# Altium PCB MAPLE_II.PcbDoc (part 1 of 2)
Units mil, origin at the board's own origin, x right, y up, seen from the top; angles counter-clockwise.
Board outline 3200 x 2150 mil, 6 copper layers (Top Side, Ground Plane, MidLayer1, MidLayer2, Power Plane, Bottom Side), stack 49.2 mil thick; 130 components, 162 nets, 713 pads, 399 vias.
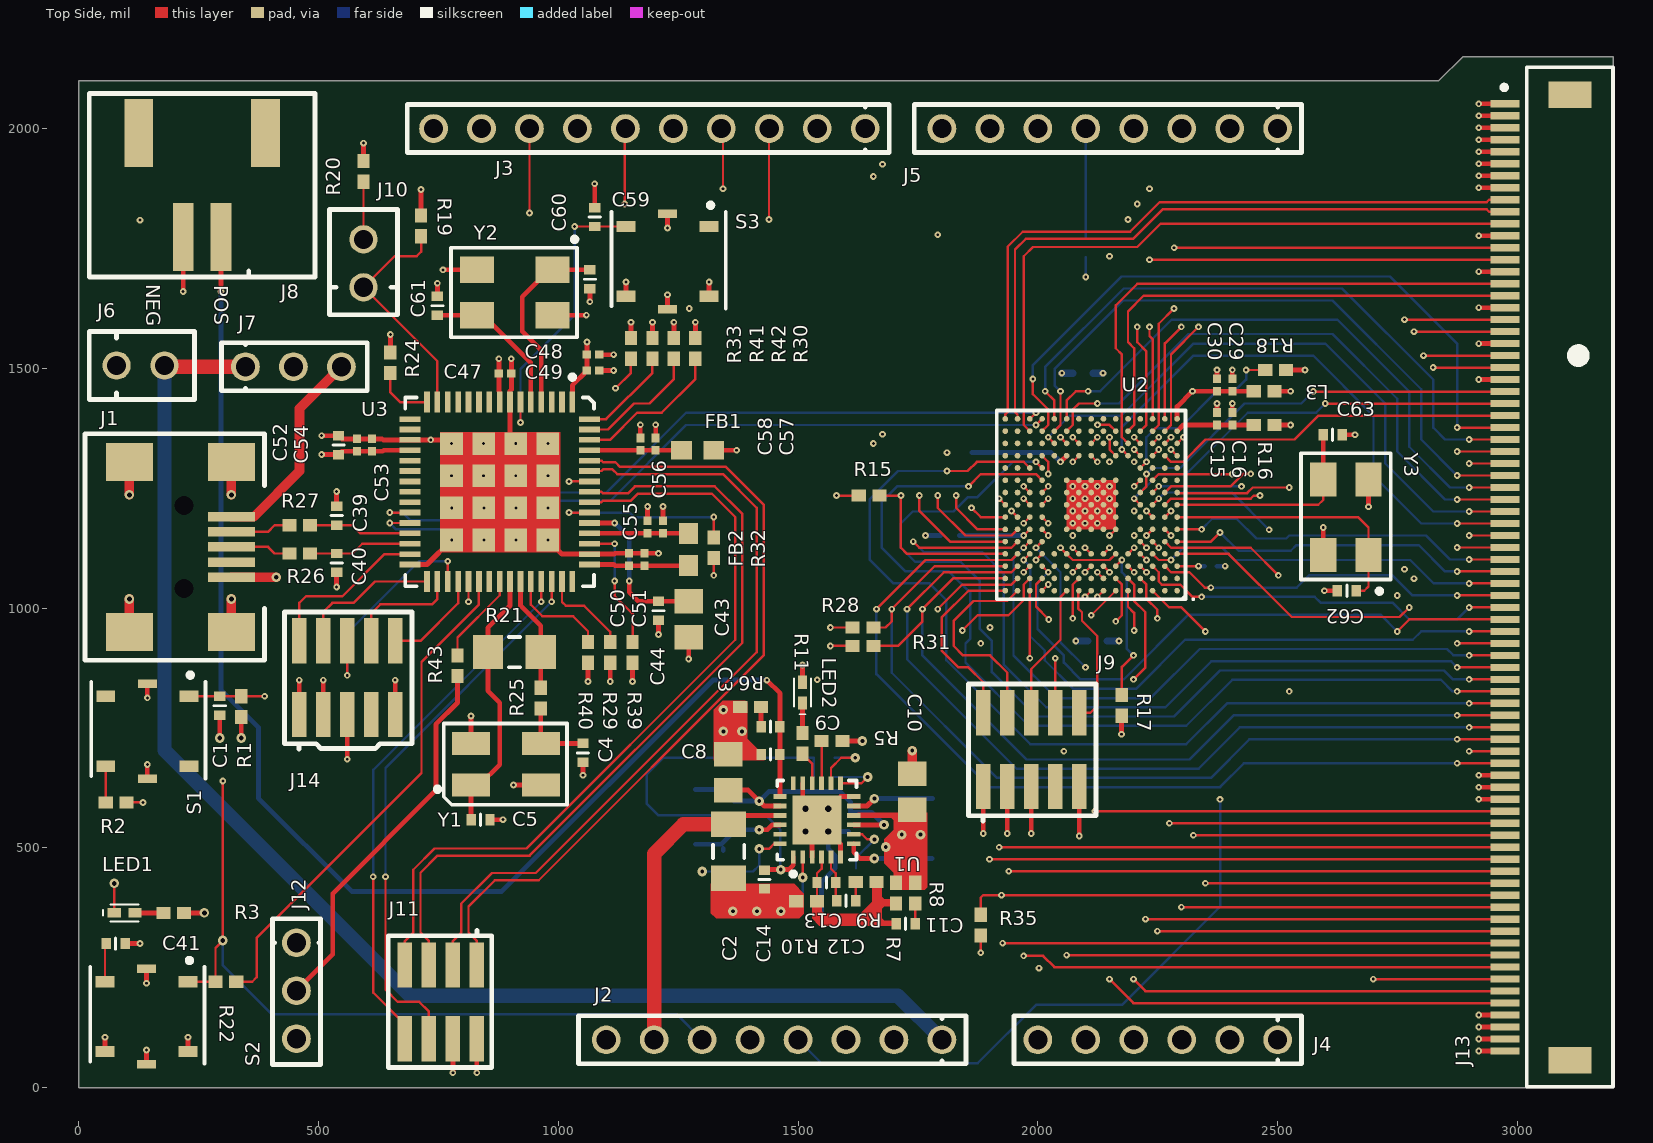
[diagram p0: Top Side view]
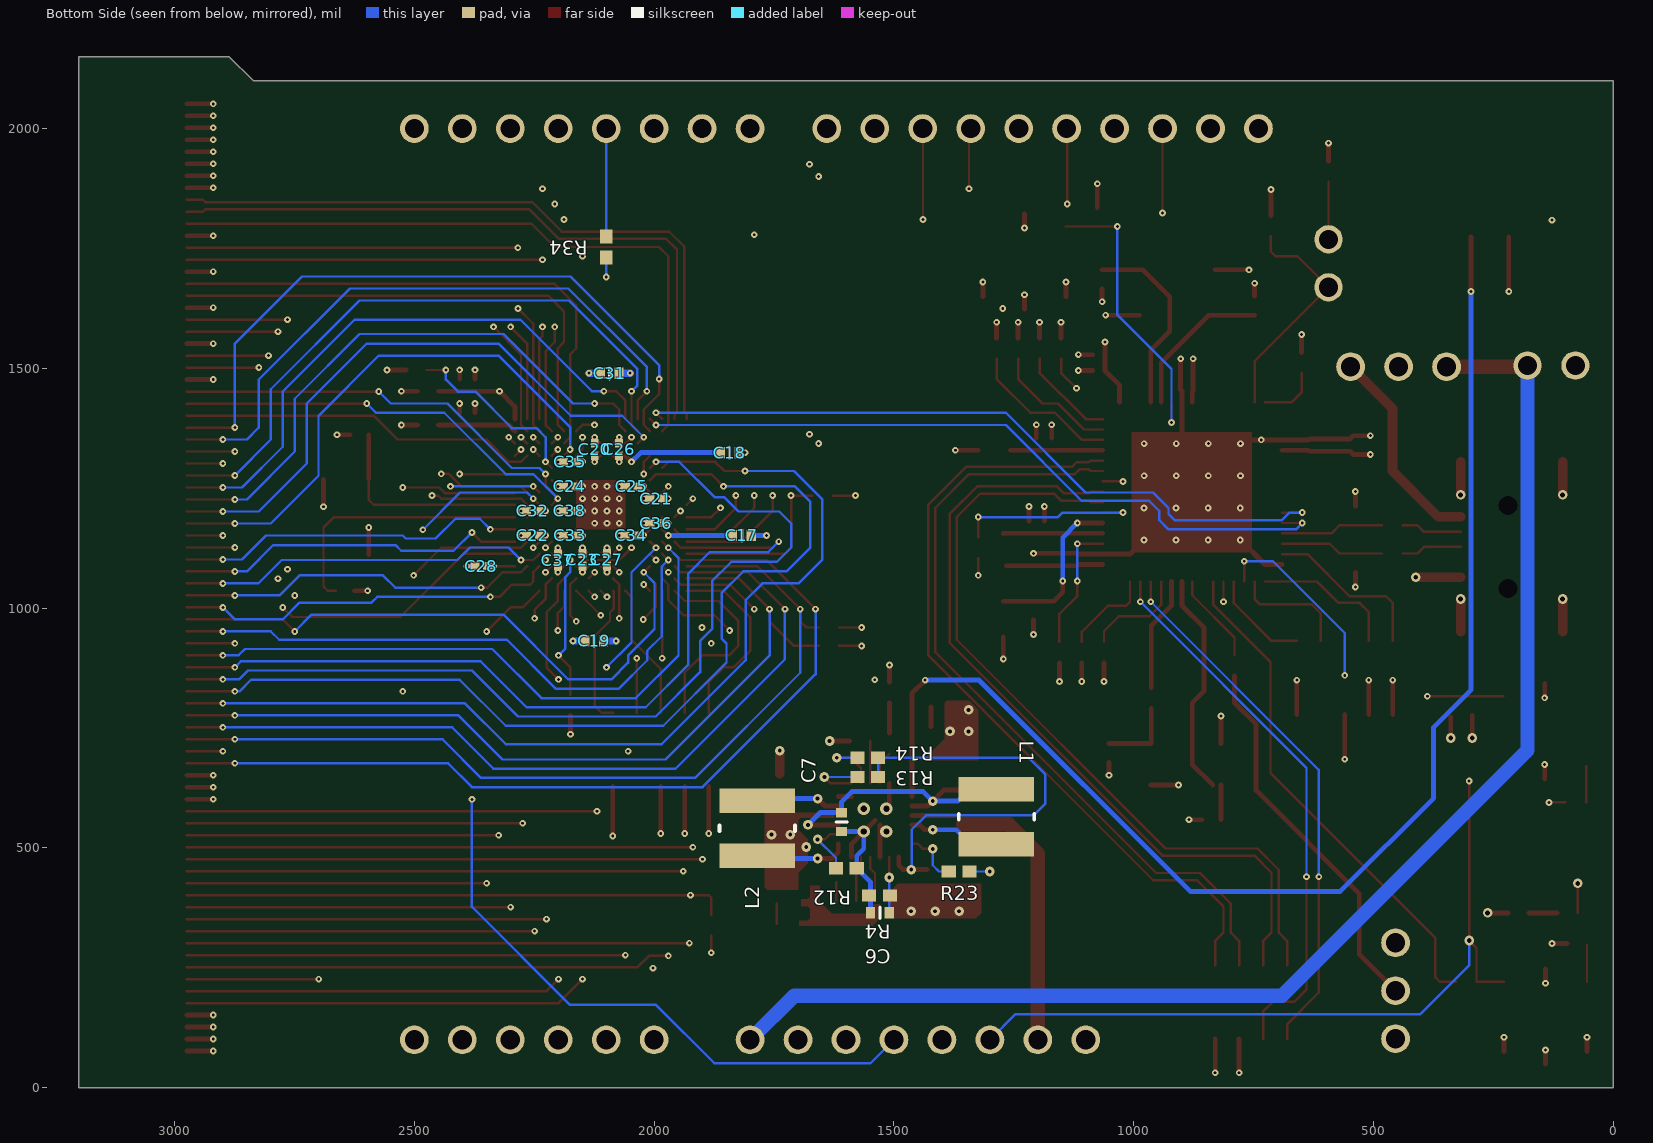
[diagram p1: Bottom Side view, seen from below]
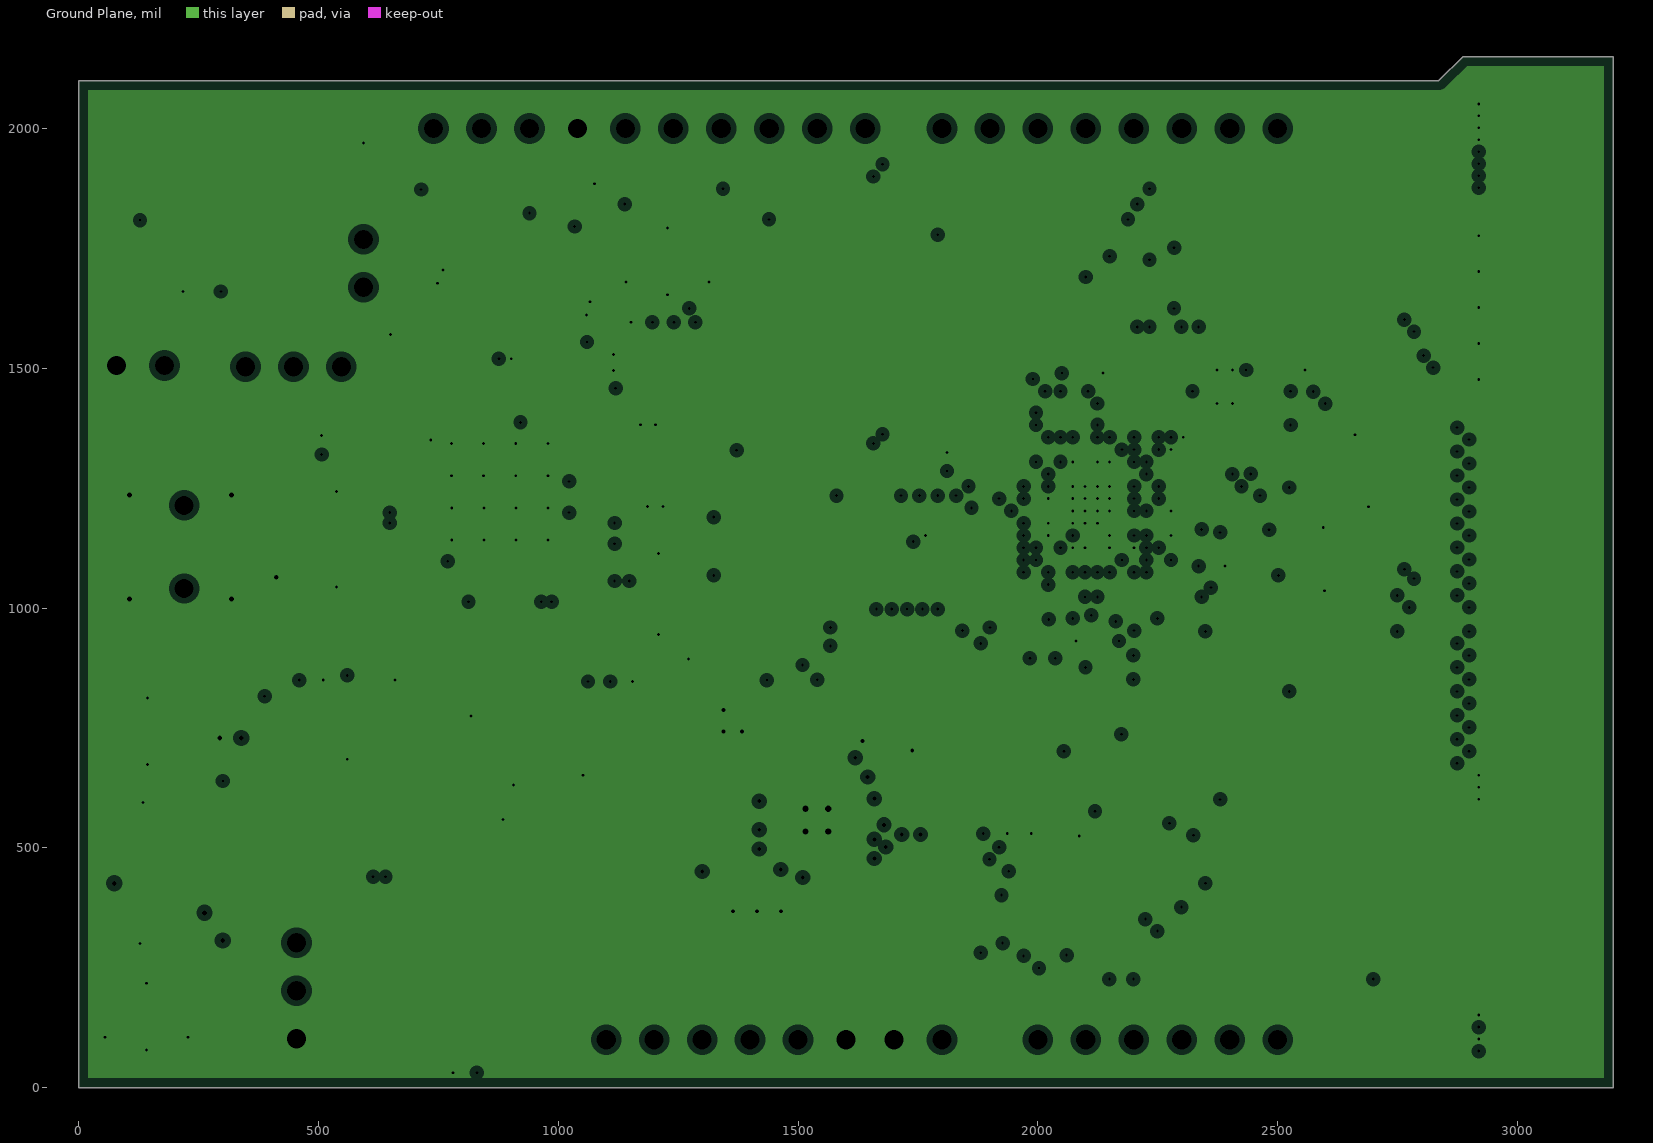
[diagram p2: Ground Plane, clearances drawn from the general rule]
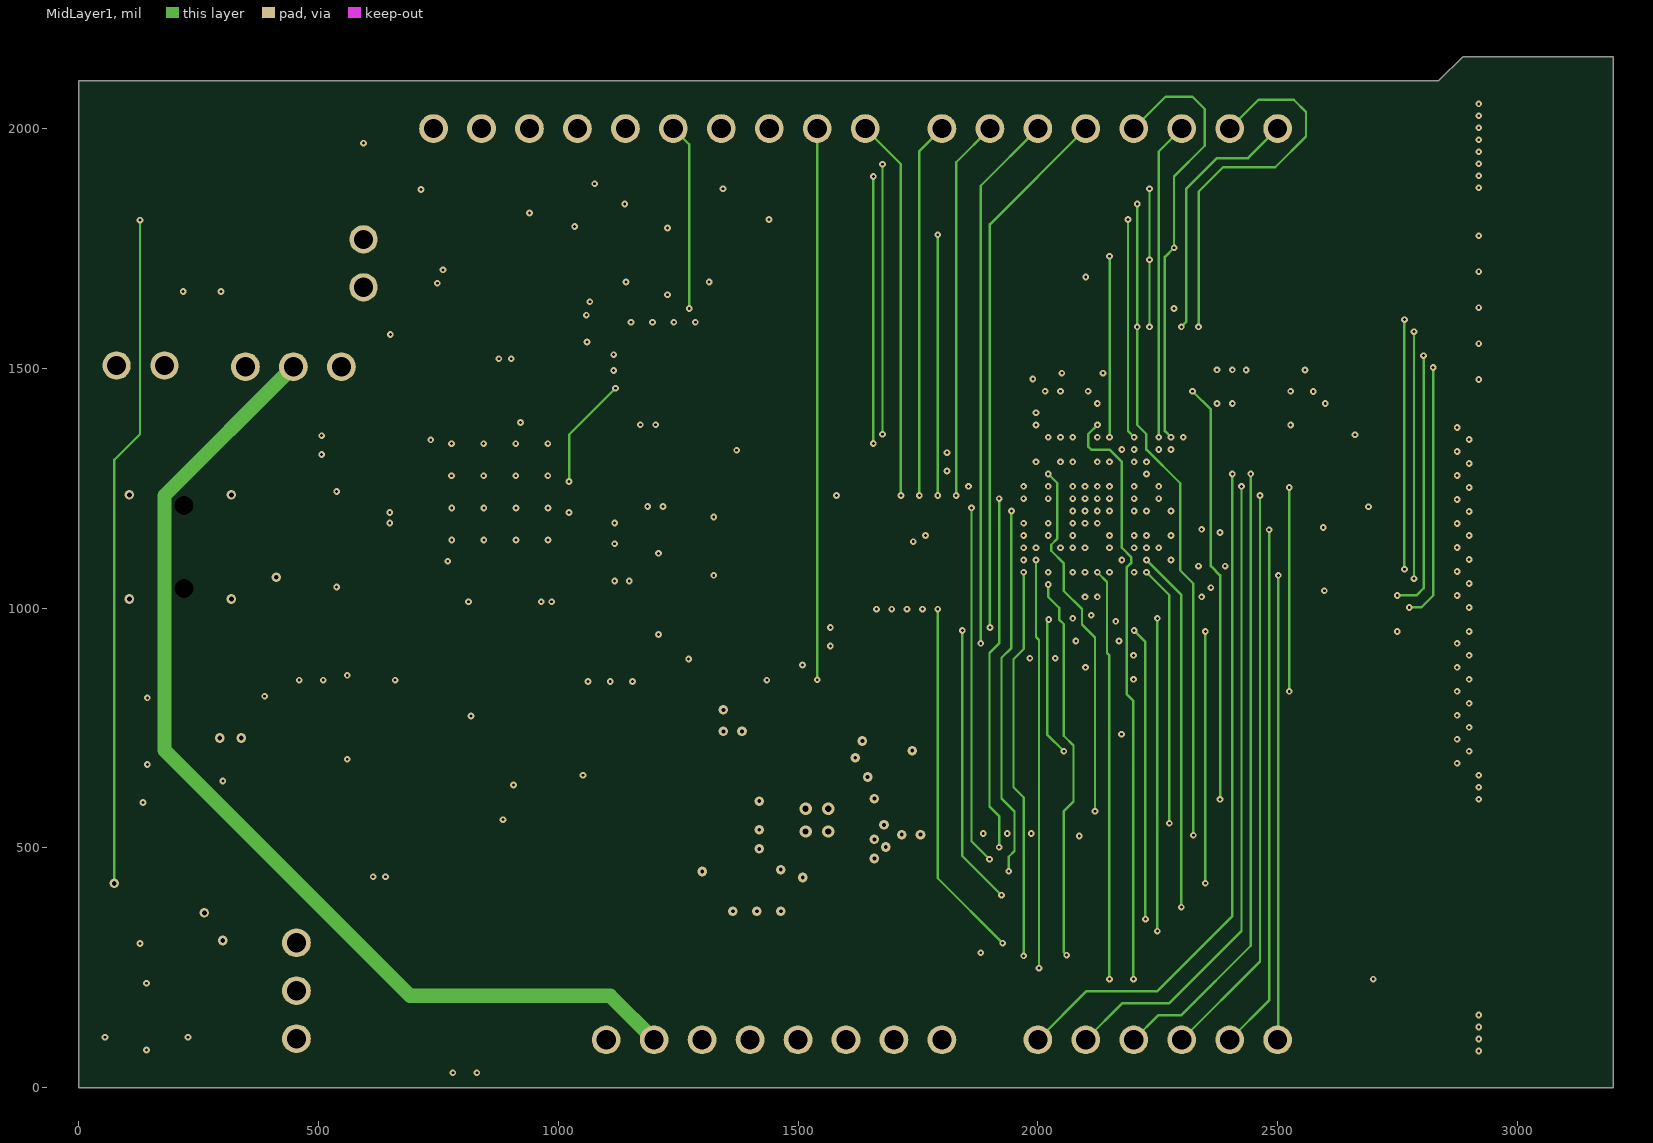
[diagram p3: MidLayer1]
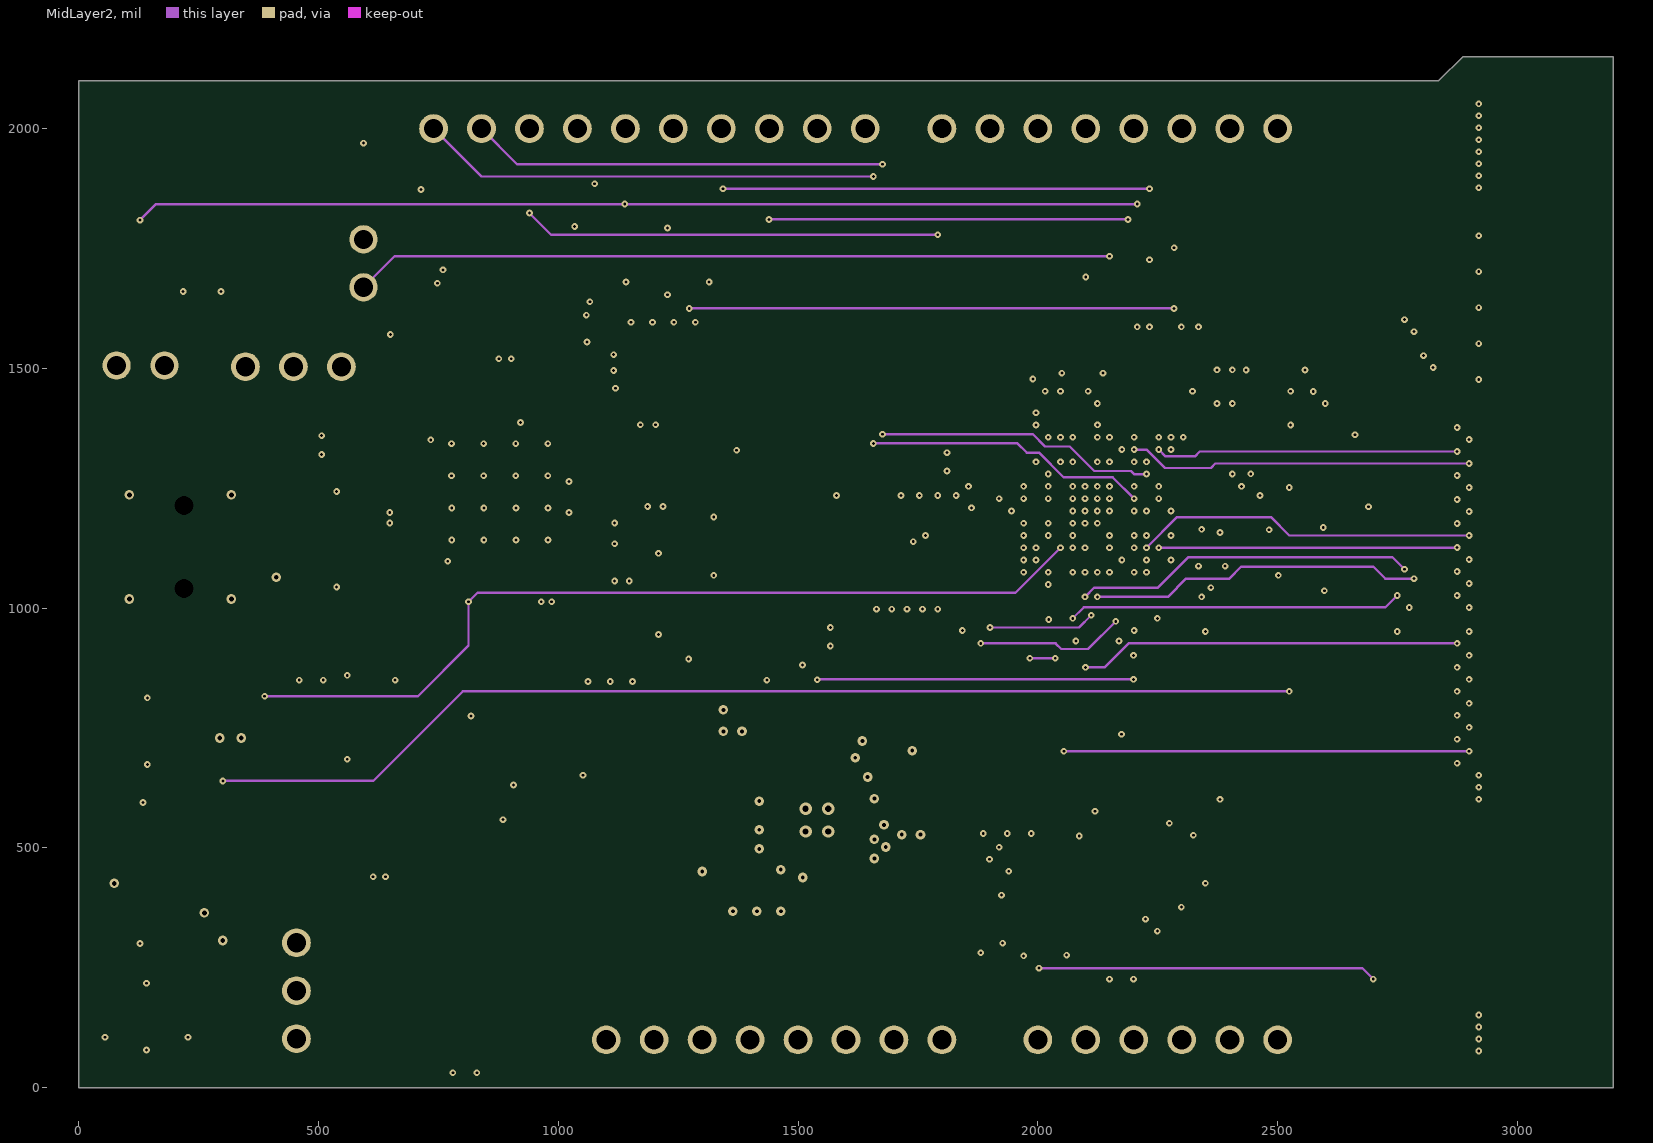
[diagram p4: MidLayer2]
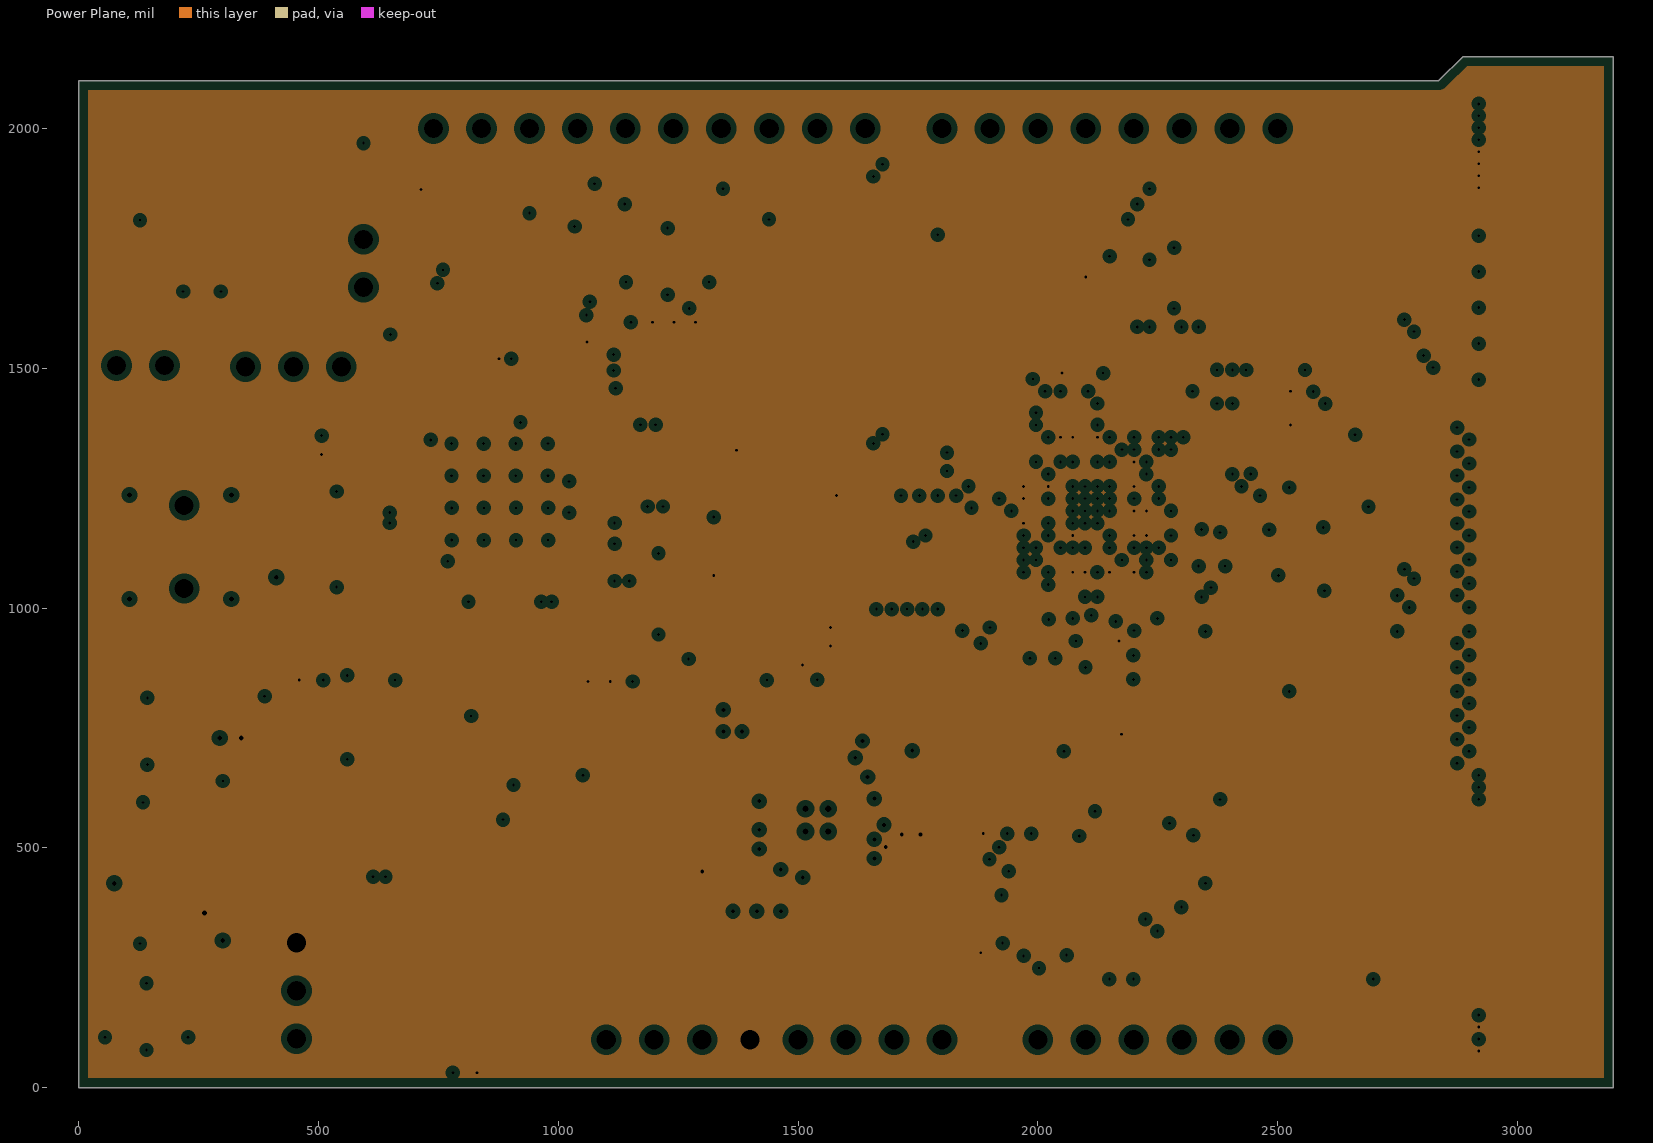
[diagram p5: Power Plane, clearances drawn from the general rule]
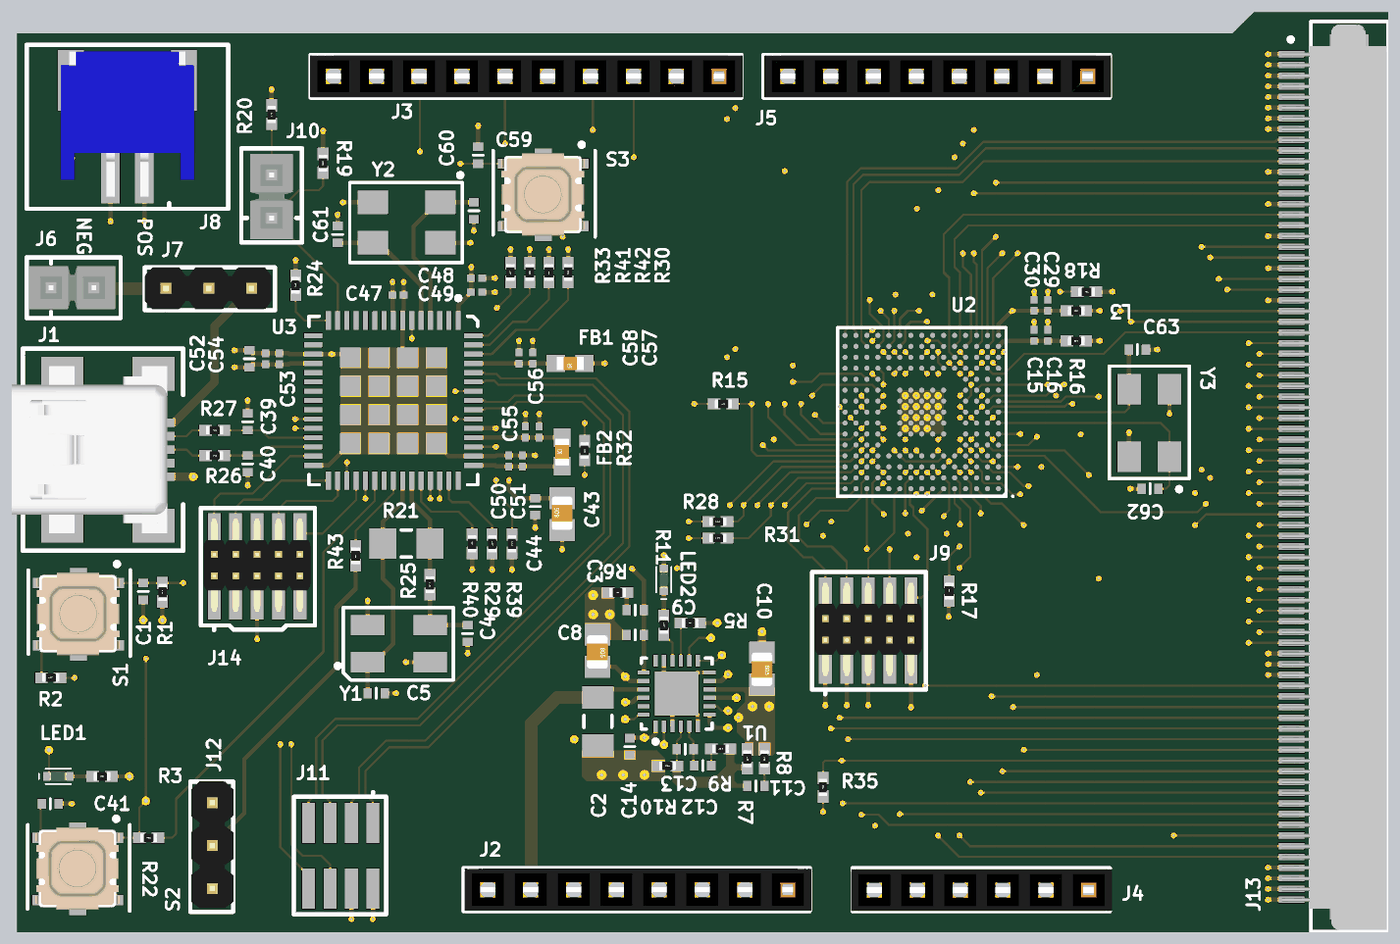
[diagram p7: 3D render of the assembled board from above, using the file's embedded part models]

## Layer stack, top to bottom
Top Side: signal copper 1.4
Dielectric: core 8, FR-4, Dk 4.8
Ground Plane: plane copper 1.4, net GND
Dielectric: prepreg 8, FR-4, Dk 4.8
MidLayer1: signal copper 1.4
Dielectric: core 8.8, FR-4, Dk 4.8
MidLayer2: signal copper 1.4
Dielectric: prepreg 8, FR-4, Dk 4.8
Power Plane: plane copper 1.4, net V3P3
Dielectric: core 8, FR-4, Dk 4.8
Bottom Side: signal copper 1.4

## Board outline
0,0 3200,0 3200,2150 2887,2150 2836,2100 0,2100

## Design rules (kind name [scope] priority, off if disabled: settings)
Clearance "Clearance~Advanced Circuits" [All] p1: gap=4 // Advanced Circuits
DiffPairsRouting [All] p1: maxlimit=12 minlimit=8 mostfreqgap=10 maxuncoupledlength=500
HoleSize "HoleSize~Sunstone Circuits" [All] p1: absolutevalues=TRUE maxlimit=251 minlimit=6 maxpercent=80.000 minpercent=20.000 // Sunstone Circuits Hole Size Rule (MLB~4&6 Layer Designs)
HoleSize Testpoint [All] p2: absolutevalues=TRUE maxlimit=100 minlimit=1 maxpercent=80.000 minpercent=20.000
HoleSize TestPointUsage [All] p3: absolutevalues=TRUE maxlimit=100 minlimit=1 maxpercent=80.000 minpercent=20.000
MinimumAnnularRing "MinimumAnnularRing~Sunstone Circuits" [All] p1: minimumring=4 // Sunstone Circuits Minimum Annular Ring (MLB~4&6 Layer Designs)
MinimumSolderMaskSliver [All] p1: minsoldermaskwidth=3
PlaneClearance "PlaneClearance~Sunstone Circuits" [All] p1: clearance=12 // Sunstone Circuits Power Plane Clearance Rule (MLB~4&6 Layer Designs)
PlaneConnect [All] p1: planeconnectstyle=Direct reliefexpansion=10 reliefentries=4 reliefconductorwidth=8 reliefairgap=10 // Sunstone Circuits Power Plane Connect Rule (MLB~4&6 Layer Designs)
PolygonConnect [All] p1: connectstyle=Direct reliefconductorwidth=8 reliefentries=4 polygonreliefangle="90 Angle" // Sunstone Circuits Polygon Connect Style (MLB~4&6 Layer Designs)
RoutingLayers [All] p1: top layer_v5=TRUE mid layer 1_v5=TRUE mid layer 2_v5=FALSE bottom layer_v5=TRUE
RoutingVias "RoutingVias~Sunstone Circuits" [All] p1: holewidth=11 width=20 viastyle="Through Hole" minholewidth=6 minwidth=14 maxholewidth=20 maxwidth=40 // Sunstone Circuits Routing Vias Rule (MLB~4&6 Layer Designs)
ShortCircuit "ShortCircuit~Sunstone Circuits" [All] p1: allowed=FALSE // Sunstone Circuits Short Circuit Rule~Do Not Allow (MLB~4&6 Layer Designs)
SilkToSilkClearance [All] p1: silktosilkclearance=5
SilkscreenOverComponentPads [All] p1: minsilkscreentomaskgap=3
SolderMaskExpansion "SolderMaskExpansion~Sunstone Circuits" [All] p1: expansion=1.5 // Sunstone Circuits Solder Mask Expansion Rule (MLB~4&6 Layer Designs)
ViasUnderSMD "ViasUnderSMD~Sunstone Circuits" [All] p1: allowed=TRUE // Sunstone Circuits Vias Under SMD~Do Not Allow (MLB~4&6 Layer Designs)
Width "Width~Advanced Circuits" [All] p1: maxlimit=100 minlimit=5 preferedwidth=10 // Advanced Circuits
19 further rules are at their usual default settings.

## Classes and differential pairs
net class HD[29..0]: HD0 HD1 HD2 HD3 HD4 HD5 HD6 HD7 HD8 HD9 HD10 HD11 HD12 HD13 HD14 HD15 HD16 HD17 HD18 HD19 HD20 HD21 HD22 HD23 HD24 HD25 HD26 HD27 HD28 HD29
net class D[16..0]: D0 D1 D2 D3 D4 D5 D6 D7 D8 D9 D10 D11 D12 D13 D14 D15 D16
net class A[5..0]: A0 A1 A2 A3 A4 A5
differential pair USB: +USB_P -USB_N
differential pair USB_COMM: +USB_COMM_P -USB_COMM_N
differential pair USB_EXT: +USB_EXT_P -USB_EXT_N
differential pair RXI: +RXI_P -RXI_N
differential pair TXO: +TXO_P -TXO_N

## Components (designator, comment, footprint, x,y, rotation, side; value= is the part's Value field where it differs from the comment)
C1 "Capacitor 1.0uF 0402 16V" C_ERA-0402 294.29,796.56 r90 top
C2 "10µF" CAP-1206 1355.25,492.99 r90 top
C3 "C_0805_22uF_25V" C_ERA-0805 1354.25,657.99 r270 top
C4 "Capacitor 18pF" C_ERA-0402 1051.52,698.31 r90 top
C5 "Capacitor 18pF" C_ERA-0402 838.02,559 r180 top
C6 "Capacitor 0.1uF 0402 16V" C_ERA-0402 1529.25,364.99 r180 bottom
C7 "Capacitor 2.2uF 0402" C_ERA-0402 1609.25,553.99 r90 bottom
C8 "Capacitor 1.0uF 0402 16V" C_ERA-0402 1442.57,694.99 r0 top
C9 "Capacitor  4.7uF 0402" C_ERA-0402 1442.57,752.99 r0 top
C10 "C_0805_22uF_25V" C_ERA-0805 1738.25,616.99 r270 top
C11 "Capacitor 33pF 0402" C_ERA-0402 1724.25,341.99 r0 top
C12 "Capacitor 330pF 0402" C_ERA-0402 1600.25,389.99 r180 top
C13 "Capacitor 10pF 0402" C_ERA-0402 1559.25,427.99 r0 top
C14 "Capacitor 1.0uF 0402 16V" C_ERA-0402 1430,434.31 r90 top
C15 "1.0UF" CAPC0201 2373.52,1394.88 r270 top
C16 "0.1UF" CAPC0201 2405.51,1394.88 r270 top
C17 "Capacitor 2.2uF 0402" C_ERA-0402 1816.93,1151.57 r0 bottom
C18 "Capacitor 2.2uF 0402" C_ERA-0402 1842.52,1324.31 r0 bottom
C19 "Capacitor  4.7uF 0402" C_ERA-0402 2125.25,931.58 r0 bottom
C20 "0.1UF" CAPC0201 2123.85,1330.89 r90 bottom
C21 "0.1UF" CAPC0201 1995.85,1228.35 r180 bottom
C22 "0.1UF" CAPC0201 2252.85,1151.57 r180 bottom
C23 "0.1UF" CAPC0201 2149.61,1100.89 r270 bottom
C24 "0.1UF" CAPC0201 2175.85,1253.89 r0 bottom
C25 "0.1UF" CAPC0201 2046.85,1253.94 r180 bottom
C26 "0.1UF" CAPC0201 2072.85,1330.89 r90 bottom
C27 "0.1UF" CAPC0201 2098.43,1100.89 r270 bottom
C28 "1.0UF" CAPC0201 2360.73,1087.6 r180 bottom
C29 "0.1UF" CAPC0201 2405.51,1465.06 r270 top
C30 "1.0UF" CAPC0201 2373.52,1465.06 r270 top
C31 "Capacitor  4.7uF 0402" C_ERA-0402 2093,1490 r180 bottom
C32 "0.1UF" CAPC0201 2252.85,1202.89 r180 bottom
C33 "0.1UF" CAPC0201 2175.2,1151.57 r0 bottom
C34 "0.1UF" CAPC0201 2047.24,1151.57 r0 bottom
C35 "0.1UF" CAPC0201 2175.2,1305.12 r0 bottom
C36 "0.1UF" CAPC0201 1995.85,1177.17 r180 bottom
C37 "0.1UF" CAPC0201 2200.79,1100.39 r270 bottom
C38 "0.1UF" CAPC0201 2175.85,1202.76 r0 bottom
C39 "Capacitor 47pF 0402 50V" C_ERA-0402 538,1193 r270 top
C40 "Capacitor 47pF 0402 50V" C_ERA-0402 538,1094.31 r90 top
C41 "C_0402_0.1UF_16V" C_ERA-0402 77.26,300.69 r180 top
C43 "C_0805_10uF_25V" C_ERA-0805 1272,977 r90 top
C44 "Capacitor 0.1uF 0402 16V" C_ERA-0402 1209,994.72 r90 top
C47 "0.1UF" CAPC0201 889,1489 r180 top
C48 "0.1UF" CAPC0201 1072.47,1528.53 r180 top
C49 "0.01UF" CAPC0201 1072.47,1495.53 r180 top
C50 "0.1UF" CAPC0201 1147.53,1101.39 r270 top
C51 "0.01UF" CAPC0201 1179.52,1101.39 r270 top
C52 "Capacitor  4.7uF 0402" C_ERA-0402 542,1340 r270 top
C53 "0.1UF" CAPC0201 612,1340 r270 top
C54 "0.01UF" CAPC0201 580,1340 r270 top
C55 "0.1UF" CAPC0201 1186.39,1168.99 r270 top
C56 "0.01UF" CAPC0201 1218.39,1169 r270 top
C57 "0.1UF" CAPC0201 1203.18,1341.99 r270 top
C58 "0.01UF" CAPC0201 1171.19,1341.99 r270 top
C59 "Capacitor 0.1uF 0402 16V" C_ERA-0402 1076,1815.43 r270 top
C60 "Capacitor 18pF 0402" C_ERA-0402 1066,1685.73 r90 top
C61 "Capacitor 18pF 0402" C_ERA-0402 748,1630.61 r270 top
C62 "Capacitor 18pF 0402" C_ERA-0402 2644.19,1036.42 r0 top
C63 "Capacitor 18pF 0402" C_ERA-0402 2614.67,1361.58 r180 top
FB1 "Ferrite Bead 120 Ohms @ 100MHz" C_ERA-0603 1290.66,1329.23 r180 top
FB2 "Ferrite Bead 120 Ohms @ 100MHz" C_ERA-0603 1272,1122.46 r90 top
J1 "USB Mini Receptical" MINI_USB_RECEPTICAL 318.5,1127.66 r0 top
J2 "J_HDR1X8_THRHOLE_VERT_RECPT" "HDR_1X8 - FEMALE" 1800,100 r180 top locked
J3 "J_HDR1X8_THRHOLE_VERT_RECPT" "HDR_1X10 - FEMALE" 1640,2000 r180 top locked
J4 "J_HDR1X6_THRHOLE_VERT_FEMALE" "HDR_1X6 - FEMALE" 2500,100 r180 top locked
J5 "J_HDR1X8_THRHOLE_VERT_RECPT" "HDR_1X8 - FEMALE" 2500,2000 r180 top locked
J6 "J_HDR1X2_JUMPER" HDR_1X2 79.13,1506 r0 top
J7 "J_HDR1X3_JUMPER_SELECT" HDR_1X3 347.83,1503.44 r0 top
J8 "J_LIPO_BAT_CONNECTOR" HDR_1X2_LIPO_BATTERY 257.37,2061.4 r0 top
J9 "J_HDR2X5_0.05_SMD" HDR_2X5_1.27MMSMD 1986.29,705.07 r0 top
J10 "J_HDR1X2_JUMPER" HDR_1X2 594,1669 r90 top
J11 "J_HDR2X4_0.05_RCP_SMD" HDR_2X4_1.27RECP_SMD 754.92,179.13 r180 top
J12 "J_HDR1X3_JUMPER_SELECT" HDR_1X3 454.23,302.36 r270 top
J13 "J_SFMH-140-02-L-D" SFMH-140 3109.25,1064.08 r0 top
J14 "J_HDR2X5_0.05_SMD" HDR_2X5_1.27MMSMD 560,855 r0 top
L1 "3.3UH 66 mOhm" INDP4040X120L 1286.25,564.99 r90 bottom
L2 "3.3UH 66 mOhm" INDP4040X120L 1785.25,540.99 r90 bottom
L3 "L_FERRITE_120R_100MHZ" ERA-0402 2471.95,1452.26 r0 top
LED1 "LED_GRN_0402" DIOM1005X07L_GREEN 95.96,364.67 r0 top
LED2 "LED_GRN_0402" DIOM1005X07L_GREEN 1509.25,823.99 r90 top
R1 "R_0402_100.0K" ERA-0402 339.07,794.59 r90 top
R2 "R_0402_10.0K" ERA-0402 78.35,594.98 r0 top
R3 "R_0402_332.0" ERA-0402 198.33,364.67 r180 top
R4 "R_0402_3.01K" ERA-0402 1530.25,400.99 r0 bottom
R5 "R_0402_1.0K" ERA-0402 1570.91,722.99 r0 top
R6 "R_0402_1.00" ERA-0402 1401.25,793.99 r180 top
R7 "R_0402_324.0K" ERA-0402 1704.25,405.99 r270 top
R8 "R_0402_121.0K" ERA-0402 1744.25,405.99 r270 top
R9 "R_0402_15.0K" ERA-0402 1641.91,428.99 r0 top
R10 "R_0402_105.0K" ERA-0402 1517.91,388.99 r180 top
R11 "R_0402_332.0" ERA-0402 1509.25,717.99 r270 top
R12 "R_0402_10.0K" ERA-0402 1599.25,457.99 r0 bottom
R13 "R_0402_10.0K" ERA-0402 1554.6,647.99 r0 bottom
R14 "R_0402_10.0K" ERA-0402 1554.6,687.99 r0 bottom
R15 "R_0402_10.0K" ERA-0402 1648.13,1234.74 r0 top
R16 "R_0402_49.9" ERA-0402 2471.95,1381.89 r180 top
R17 "R_0402_0.0" ERA-0402 2175.2,797.24 r270 top
R18 "R_0402_10.0K" ERA-0402 2495.91,1496.58 r0 top
R19 "R_0402_10.0K" ERA-0402 714,1797 r90 top
R20 "R_0402_1.0K" ERA-0402 594,1910.65 r90 top
R21 "R_1206_1.0M" R_ERA-1206 908.46,908.46 r0 top
R22 "R_0402_1.0K" ERA-0402 307,221.16 r0 top
R23 "R_0402_10.0K" ERA-0402 1364.25,450.99 r180 bottom
R24 "R_0402_10.0K" ERA-0402 650,1511.65 r90 top
R25 "R_0402_0.0" ERA-0402 963.58,812.5 r270 top
R26 "R_0402_22.0" ERA-0402 461,1114 r0 top
R27 "R_0402_22.0" ERA-0402 461,1173 r0 top
R28 "R_0402_10.0K" ERA-0402 1635.33,959.65 r0 top
R29 "R_0402_10.0K" ERA-0402 1108.5,908 r270 top
R30 "R_0402_10.0K" ERA-0402 1285.93,1541.83 r90 top
R31 "R_0402_10.0K" ERA-0402 1635.33,921.26 r0 top
R32 "R_0402_10.0K" ERA-0402 1324.31,1125.98 r270 top
R33 "R_0402_10.0K" ERA-0402 1151.57,1541.83 r90 top
R34 "R_0402_10.0K" ERA-0402 2100,1752.95 r90 bottom
R35 "R_0402_10.0K" ERA-0402 1880.91,339.07 r90 top
R39 "R_0402_28.7K" ERA-0402 1155,908 r270 top
R40 "R_0402_10.0K" ERA-0402 1062.01,908 r90 top
R41 "R_0402_10.0K" ERA-0402 1196.36,1541.83 r270 top
R42 "R_0402_10.0K" ERA-0402 1241.14,1541.83 r270 top
R43 "R_0402_10.0K" ERA-0402 790,880 r90 top
S1 "S_TACTILE_5X5" TACTILE_BUTTON_5X5 143.31,743.41 r270 top
S2 "S_TACTILE_5X5" TACTILE_BUTTON_5X5 141.61,148.33 r270 top
S3 "S_TACTILE_5X5" TACTILE_BUTTON_5X5 1228.02,1722.91 r270 top
U1 "5V USB/DC Bat Charger PMIC" QFN50P400X400X100-24L 1539.25,557.99 r90 top
U2 "U_MC-ARM-STM32F407" UFBGA176+25 2111.22,1215.55 r180 top
U3 "Wiznet 7200" LCCS55P1000X1000X150-60L 877.95,1242.62 r270 top
Y1 "25.00MHz Crystal" LCCS220P500X320X105-4L 891.17,674.69 r0 top
Y2 "8MHz" SMD_OSC_8MHZ 909.16,1658.17 r180 top
Y3 "8MHz" SMD_OSC_8MHZ 2642.22,1189.96 r90 top

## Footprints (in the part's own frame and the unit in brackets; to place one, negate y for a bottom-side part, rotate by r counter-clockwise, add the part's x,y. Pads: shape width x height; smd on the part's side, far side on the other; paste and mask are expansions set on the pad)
C_ERA-0402 [mm]
  rect 0.5x0.6 smd: 1(-0.5,0) 2(0.5,0)
  silkscreen extent 0,-0.3 0,0.3, body extent -0.51,-0.3 0.51,0.3, height 0.2
C_ERA-0603 [mm]
  rect 1.1x1 smd: 1(-0.85,0) 2(0.85,0)
  body extent -0.8,-0.4 0.8,0.4, height 0.3
C_ERA-0805 [mm]
  rect 1.3x1.5 smd: 1(-0.95,0) 2(0.95,0)
  body extent -0.94,-0.62 1.06,0.63, height 0.78
CAP-1206 [mm] "Chip Capacitor, 2-Leads, Body 1206, IPC Medium Density"
  rect 1.35x1.85 smd: 1(-1.425,0) 2(1.425,0)
  silkscreen extent -0.35,-0.82 0.35,0.82, body extent -1.7,-0.9 1.7,0.9, height 1.8
CAPC0201 [mm] "Chip Capacitor, Body 0.6x0.3mm, Height 0.33mm, IPC Medium Density"
  rect 0.46x0.42 smd: 1(-0.33,0) 2(0.33,0)
  body extent -0.31,-0.16 0.32,0.17, height 0.33
DIOM1005X07L_GREEN [mm] "Molded Diode, 2-Leads, Body 1.0x0.5mm, IPC High Density"
  rect 0.7x0.5 smd: 1(0.55,0) 2(-0.55,0)
  silkscreen extent -1.15,-0.45 0.75,0.45, body extent -0.5,-0.25 0.51,0.25, height 0.45
ERA-0402 [mm] "Chip Resistor, 2-Leads, Body 1.0x0.5mm, IPC Medium Density"
  rect 0.75x0.65 smd: 1(-0.55,0) 2(0.55,0)
  body extent -0.5,-0.25 0.5,0.25, height 0.33
HDR_1X2 [mm] "Jumper"
  round 1.5 hole 1.016: 1(0,0) 2(2.54,0)
  silkscreen extent -1.45,-1.8 4.13,1.8, body extent -1.27,-1.27 3.81,1.27, height 8.38
HDR_1X2_LIPO_BATTERY [mm] "POWER CONNECTOR"
  rect 1.1x3.6 smd: 1(1,-7.3) 2(-1,-7.3)
  rect 1.53x3.6 smd: MNT(-3.35,-1.8) MNT(3.35,-1.8)
  silkscreen extent -5.97,-9.43 5.97,0.3, body extent -3.95,-8.7 3.95,-0.1, height 5.63
HDR_1X3 [mil] "HEADER"
  round 60 hole 40: 1(0,0) 2(100,0) 3(200,0)
  silkscreen extent -50,-50 254,50, body extent -51,-48 245,50, height 329
"HDR_1X6 - FEMALE" [mil] "HEADER"
  round 60 hole 40: 1(0,0) 2(100,0) 3(200,0) 4(300,0) 5(400,0) 6(500,0)
  silkscreen extent -50,-50 550,50, body extent -56,-48 554,50, height 340
"HDR_1X8 - FEMALE" [mil] "FEMALE HEADER"
  round 60 hole 40: 1(0,0) 2(100,0) 3(200,0) 4(300,0) 5(400,0) 6(500,0) 7(600,0) 8(700,0)
  silkscreen extent -50,-50 758,50, body extent -54,-49 756,49, height 340
"HDR_1X10 - FEMALE" [mil] "FEMALE HEADER"
  round 60 hole 40: 1(0,0) 2(100,0) 3(200,0) 4(300,0) 5(400,0) 6(500,0) 7(600,0) 8(700,0) 9(800,0) 10(900,0)
  silkscreen extent -50,-50 955,50, body extent -53,-49 957,49, height 340
HDR_2X4_1.27RECP_SMD [mm] "8 pin header"
  rect 0.76x2.4 smd mask+0.05: 1(-1.915,-1.95) 2(-1.915,1.95) 3(-0.645,-1.95) 4(-0.645,1.95) 5(0.625,-1.95) 6(0.625,1.95) 7(1.895,-1.95) 8(1.895,1.95)
  silkscreen extent -2.7,-3.78 2.78,3.47
HDR_2X5_1.27MMSMD [mm] "10 pin header"
  rect 0.76x2.4 smd mask+0.05: 1(-2.54,-1.95) 2(-2.54,1.95) 3(-1.27,-1.95) 4(-1.27,1.95) 5(0,-1.95) 6(0,1.95) 7(1.27,-1.95) 8(1.27,1.95) 9(2.54,-1.95) 10(2.54,1.95)
  silkscreen extent -3.32,-3.78 3.42,3.47, body extent -3.17,-2.68 3.18,2.83, height 6.4
INDP4040X120L [mm] "Precision Wire Wound Inductor, 2-Leads, Body 4.0x4.0mm, IPC High Density"
  rect 1.3x4 smd: 1(-1.45,0) 2(1.45,0)
  silkscreen extent -0.15,-2 0.15,2, body extent -2,-2 2,2.01, height 0.3
LCCS55P1000X1000X150-60L [mm] "LCC, 60-Pins, Body 10.0x10.0mm (max), Pitch 0.55mm, IPC High Density"
  rect 1.1x0.3 smd: 1(-4.75,3.85) 2(-4.75,3.3) 3(-4.75,2.75) 4(-4.75,2.2) 5(-4.75,1.65) 6(-4.75,1.1) 7(-4.75,0.55) 8(-4.75,0) 9(-4.75,-0.55) 10(-4.75,-1.1) 11(-4.75,-1.65) 12(-4.75,-2.2) 13(-4.75,-2.75) 14(-4.75,-3.3) 15(-4.75,-3.85) 31(4.75,-3.85) 32(4.75,-3.3) 33(4.75,-2.75) 34(4.75,-2.2) 35(4.75,-1.65) 36(4.75,-1.1) 37(4.75,-0.55) 38(4.75,0) 39(4.75,0.55) 40(4.75,1.1) 41(4.75,1.65) 42(4.75,2.2) 43(4.75,2.75) 44(4.75,3.3) 45(4.75,3.85)
  rect 0.3x1.1 smd: 16(-3.85,-4.75) 17(-3.3,-4.75) 18(-2.75,-4.75) 19(-2.2,-4.75) 20(-1.65,-4.75) 21(-1.1,-4.75) 22(-0.55,-4.75) 23(0,-4.75) 24(0.55,-4.75) 25(1.1,-4.75) 26(1.65,-4.75) 27(2.2,-4.75) 28(2.75,-4.75) 29(3.3,-4.75) 30(3.85,-4.75) 46(3.85,4.75) 47(3.3,4.75) 48(2.75,4.75) 49(2.2,4.75) 50(1.65,4.75) 51(1.1,4.75) 52(0.55,4.75) 53(0,4.75) 54(-0.55,4.75) 55(-1.1,4.75) 56(-1.65,4.75) 57(-2.2,4.75) 58(-2.75,4.75) 59(-3.3,4.75) 60(-3.85,4.75)
  rect 1.2x1.2 smd: PAD1(-2.55,2.55) PAD2(-0.85,2.55) PAD3(0.85,2.55) PAD4(2.55,2.55) PAD5(-2.55,0.85) PAD6(-0.85,0.85) PAD7(0.85,0.85) PAD8(2.55,0.85) PAD9(-2.55,-0.85) PAD10(-0.85,-0.85) PAD11(0.85,-0.85) PAD12(2.55,-0.85) PAD13(-2.55,-2.55) PAD14(-0.85,-2.55) PAD15(0.85,-2.55) PAD16(2.55,-2.55)
  silkscreen extent -6.2,-5 5,5, body extent -5,-5 5,5, height 1.5
LCCS220P500X320X105-4L [mm] "LCC, 4-Pins, Body 5.0x3.3mm (max), Pitch 2.20mm, IPC High Density"
  rect 2x1.2 smd: 1(-1.85,-1.1) 2(1.85,-1.1) 3(1.85,1.1) 4(-1.85,1.1)
  silkscreen extent -3.75,-2.15 3.22,2.15, body extent -2.5,-1.6 2.5,1.6, height 1.05
MINI_USB_RECEPTICAL [mm] "MINI USB, R/A, SMT, B TYPE"
  rect 2.5x0.5 smd: 1(0,1.6) 2(0,0.8) 3(0,0) 4(0,-0.8) 5(0,-1.6)
  rect 2.5x2 smd: S(-5.4,-4.5) S(-5.4,4.5) S(0,-4.5) S(0,4.5)
  round 0 hole 1: ""(-2.5,-2.2) ""(-2.5,2.2)
  silkscreen extent -7.75,-6 1.75,6, body extent -8.4,-4.95 0.8,4.95, height 4.14
QFN50P400X400X100-24L [mm] "QFN, 24-Leads, Body 4.2x4.2mm (max), Pitch 0.50mm, IPC High Density"
  rect 0.7x0.25 smd mask+0.05: 1(-1.95,1.25) 2(-1.95,0.75) 3(-1.95,0.25) 4(-1.95,-0.25) 5(-1.95,-0.75) 6(-1.95,-1.25) 13(1.95,-1.25) 14(1.95,-0.75) 15(1.95,-0.25) 16(1.95,0.25) 17(1.95,0.75) 18(1.95,1.25)
  rect 0.25x0.7 smd mask+0.05: 7(-1.25,-1.95) 8(-0.75,-1.95) 9(-0.25,-1.95) 10(0.25,-1.95) 11(0.75,-1.95) 12(1.25,-1.95) 19(1.25,1.95) 20(0.75,1.95) 21(0.25,1.95) 22(-0.25,1.95) 23(-0.75,1.95) 24(-1.25,1.95)
  rect 2.6x2.6 smd mask+0.05: 25(0,0)
  silkscreen extent -2.97,-2.1 2.1,2.1, body extent -2.08,-2.07 2.07,2.08, height 1
R_ERA-1206 [mm]
  rect 1.6x1.8 smd: 1(-1.4,0) 2(1.4,0)
  silkscreen extent -0.3,-0.8 0.3,0.8, body extent -1.6,-0.8 1.6,0.8, height 1
SFMH-140 [mil] "SFMH-140"
  rect 60x15 smd mask+2.36: 1(-135,962.5) 2(-135,987.5) 3(-135,912.5) 4(-135,937.5) 5(-135,862.5) 6(-135,887.5) 7(-135,812.5) 8(-135,837.5) 9(-135,762.5) 10(-135,787.5) 11(-135,712.5) 12(-135,737.5) 13(-135,662.5) 14(-135,687.5) 15(-135,612.5) 16(-135,637.5) 17(-135,562.5) 18(-135,587.5) 19(-135,512.5) 20(-135,537.5) 21(-135,462.5) 22(-135,487.5) 23(-135,412.5) 24(-135,437.5) 25(-135,362.5) 26(-135,387.5) 27(-135,312.5) 28(-135,337.5) 29(-135,262.5) 30(-135,287.5) 31(-135,212.5) 32(-135,237.5) 33(-135,162.5) 34(-135,187.5) 35(-135,112.5) 36(-135,137.5) 37(-135,62.5) 38(-135,87.5) 39(-135,12.5) 40(-135,37.5) 41(-135,-37.5) 42(-135,-12.5) 43(-135,-87.5) 44(-135,-62.5) 45(-135,-137.5) 46(-135,-112.5) 47(-135,-187.5) 48(-135,-162.5) 49(-135,-237.5) 50(-135,-212.5) 51(-135,-287.5) 52(-135,-262.5) 53(-135,-337.5) 54(-135,-312.5) 55(-135,-387.5) 56(-135,-362.5) 57(-135,-437.5) 58(-135,-412.5) 59(-135,-487.5) 60(-135,-462.5) 61(-135,-537.5) 62(-135,-512.5) 63(-135,-587.5) 64(-135,-562.5) 65(-135,-637.5) 66(-135,-612.5) 67(-135,-687.5) 68(-135,-662.5) 69(-135,-737.5) 70(-135,-712.5) 71(-135,-787.5) 72(-135,-762.5) 73(-135,-837.5) 74(-135,-812.5) 75(-135,-887.5) 76(-135,-862.5) 77(-135,-937.5) 78(-135,-912.5) 79(-135,-987.5) 80(-135,-962.5)
  rect 90x55 smd mask+0: M1(0,1006.5) M2(0,-1006.5)
  silkscreen extent -142,-1062 90,1064, body extent -157,-1058 88,1057, height 134
SMD_OSC_8MHZ [mm]
  rect 1.8x1.4 smd: 1(-2,-1.2) 2(2,-1.2) 3(2,1.2) 4(-2,1.2)
  silkscreen extent -3.3,-2.94 3.37,2.37, body extent -2.9,-2 2.9,2, height 1.7
TACTILE_BUTTON_5X5 [mm] "LCC, 8-Pins, Body 6.5x6.0mm (max), Pitch 1.27mm, IPC Medium Density"
  rect 0.6x1 smd: 1(-1.85,2.2) 2(-1.85,-2.2) 3(1.85,-2.2) 4(1.85,2.2)
  rect 0.45x1 smd: 5(-2.525,0) 6(2.525,0)
  silkscreen extent -3.1,-2.98 2.5,3.08, body extent -2.47,-2.52 2.42,2.47, height 1.5
UFBGA176+25 [mm] "BGA, 201-Leads, Body 10x10mm, Pitch 0.65mm"
  round 0.3 smd mask+0: A1(-4.55,4.55) A2(-3.9,4.55) A3(-3.25,4.55) A4(-2.6,4.55) A5(-1.95,4.55) A6(-1.3,4.55) A7(-0.65,4.55) A8(0,4.55) A9(0.65,4.55) A10(1.3,4.55) A11(1.95,4.55) A12(2.6,4.55) A13(3.25,4.55) A14(3.9,4.55) A15(4.55,4.55) B1(-4.55,3.9) B2(-3.9,3.9) B3(-3.25,3.9) B4(-2.6,3.9) B5(-1.95,3.9) B6(-1.3,3.9) B7(-0.65,3.9) B8(0,3.9) B9(0.65,3.9) B10(1.3,3.9) B11(1.95,3.9) B12(2.6,3.9) B13(3.25,3.9) B14(3.9,3.9) B15(4.55,3.9) C1(-4.55,3.25) C2(-3.9,3.25) C3(-3.25,3.25) C4(-2.6,3.25) C5(-1.95,3.25) C6(-1.3,3.25) C7(-0.65,3.25) C8(0,3.25) C9(0.65,3.25) C10(1.3,3.25) C11(1.95,3.25) C12(2.6,3.25) C13(3.25,3.25) C14(3.9,3.25) C15(4.55,3.25) D1(-4.55,2.6) D2(-3.9,2.6) D3(-3.25,2.6) D4(-2.6,2.6) D5(-1.95,2.6) D6(-1.3,2.6) D7(-0.65,2.6) D8(0,2.6) D9(0.65,2.6) D10(1.3,2.6) D11(1.95,2.6) D12(2.6,2.6) D13(3.25,2.6) D14(3.9,2.6) D15(4.55,2.6) E1(-4.55,1.95) E2(-3.9,1.95) E3(-3.25,1.95) E4(-2.6,1.95) E12(2.6,1.95) E13(3.25,1.95) E14(3.9,1.95) E15(4.55,1.95) F1(-4.55,1.3) F2(-3.9,1.3) F3(-3.25,1.3) F4(-2.6,1.3) F6(-1.3,1.3) F7(-0.65,1.3) F8(0,1.3) F9(0.65,1.3) F10(1.3,1.3) F12(2.6,1.3) F13(3.25,1.3) F14(3.9,1.3) F15(4.55,1.3) G1(-4.55,0.65) G2(-3.9,0.65) G3(-3.25,0.65) G4(-2.6,0.65) G6(-1.3,0.65) G7(-0.65,0.65) G8(0,0.65) G9(0.65,0.65) G10(1.3,0.65) G12(2.6,0.65) G13(3.25,0.65) G14(3.9,0.65) G15(4.55,0.65) H1(-4.55,0) H2(-3.9,0) H3(-3.25,0) H4(-2.6,0) H6(-1.3,0) H7(-0.65,0) H8(0,0) H9(0.65,0) H10(1.3,0) H12(2.6,0) H13(3.25,0) H14(3.9,0) H15(4.55,0) J1(-4.55,-0.65) J2(-3.9,-0.65) J3(-3.25,-0.65) J4(-2.6,-0.65) J6(-1.3,-0.65) J7(-0.65,-0.65) J8(0,-0.65) J9(0.65,-0.65) J10(1.3,-0.65) J12(2.6,-0.65) J13(3.25,-0.65) J14(3.9,-0.65) J15(4.55,-0.65) K1(-4.55,-1.3) K2(-3.9,-1.3) K3(-3.25,-1.3) K4(-2.6,-1.3) K6(-1.3,-1.3) K7(-0.65,-1.3) K8(0,-1.3) K9(0.65,-1.3) K10(1.3,-1.3) K12(2.6,-1.3) K13(3.25,-1.3) K14(3.9,-1.3) K15(4.55,-1.3) L1(-4.55,-1.95) L2(-3.9,-1.95) L3(-3.25,-1.95) L4(-2.6,-1.95) L12(2.6,-1.95) L13(3.25,-1.95) L14(3.9,-1.95) L15(4.55,-1.95) M1(-4.55,-2.6) M2(-3.9,-2.6) M3(-3.25,-2.6) M4(-2.6,-2.6) M5(-1.95,-2.6) M6(-1.3,-2.6) M7(-0.65,-2.6) M8(0,-2.6) M9(0.65,-2.6) M10(1.3,-2.6) M11(1.95,-2.6) M12(2.6,-2.6) M13(3.25,-2.6) M14(3.9,-2.6) M15(4.55,-2.6) N1(-4.55,-3.25) N2(-3.9,-3.25) N3(-3.25,-3.25) N4(-2.6,-3.25) N5(-1.95,-3.25) N6(-1.3,-3.25) N7(-0.65,-3.25) N8(0,-3.25) N9(0.65,-3.25) N10(1.3,-3.25) N11(1.95,-3.25) N12(2.6,-3.25) N13(3.25,-3.25) N14(3.9,-3.25) N15(4.55,-3.25) P1(-4.55,-3.9) P2(-3.9,-3.9) P3(-3.25,-3.9) P4(-2.6,-3.9) P5(-1.95,-3.9) P6(-1.3,-3.9) P7(-0.65,-3.9) P8(0,-3.9) P9(0.65,-3.9) P10(1.3,-3.9) P11(1.95,-3.9) P12(2.6,-3.9) P13(3.25,-3.9) P14(3.9,-3.9) P15(4.55,-3.9) R1(-4.55,-4.55) R2(-3.9,-4.55) R3(-3.25,-4.55) R4(-2.6,-4.55) R5(-1.95,-4.55) R6(-1.3,-4.55) R7(-0.65,-4.55) R8(0,-4.55) R9(0.65,-4.55) R10(1.3,-4.55) R11(1.95,-4.55) R12(2.6,-4.55) R13(3.25,-4.55) R14(3.9,-4.55) R15(4.55,-4.55)
  silkscreen extent -5.45,-5 5,5.05, body extent -5,-5 5,5, height 0.61

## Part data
C1 C8 C14: library part C_0402_1.0UF_16V, "CAP CER 1.0UF 16V X5R 0402"
C2: library part C_1206_10UF_25V, "CAP CER 10UF 25V X5R 1206"
C3 C10: library part C_0805_22UF_6.3V, "CAP CER 22UF 6.3V X7R 10% 0805"
C4 C5 C60 C61 C62 C63: library part C_0402_18PF_50V, "CAP CER 18PF 50V C0G 5% 0402"
C6 C44 C59: library part C_0402_0.1UF_16V, "CAP CER .10UF 16V X7R 0402"
C7 C17 C18: library part C_0402_2.2UF, "CAP CER 2.2UF 6.3V X5R 0402"
C9 C19 C31 C52: library part C_0402_4.7UF, "CAP CER 4.7UF 6.3V X5R 0402"
C11: library part C_0402_33PF, "CAP CER 33PF 50V C0G 5% 0402"
C12: library part C_0402_330PF_50V, "CAP CER 330PF 50V 5% NP0 0402"
C13: library part C_0402_10PF_50V, "CAP CER 10PF 50V NP0 0402"
C15 C28 C30: library part C_0201_1.0UF, "CAP CER 1UF 6.3V 20% X5R 0201"
C16 C20 C21 C22 C23 C24 C25 C26 C27 C29 C32 C33 C34 C35 C36 C37 C38 C47 C48 C50 C53 C55 C57: library part C_0201_0.1UF, "CAP CER 0.1UF 6.3V 10% X5R 0201"
C39 C40: library part C_0402_47p_50V, "CAP CER 47PF 50V 5% C0G 0402"
C41: "CAP CER .10UF 16V X7R 0402"
C43: library part C_0805_10UF_6.3V, "CAP CER 10UF 6.3V X7R 10% 0805"
C49 C51 C54 C56 C58: library part C_0201_0.01UF, "CAP CER 10000PF 6.3V X5R 0201"
FB1 FB2: library part FB_0603_120_100MHZ, "FERRITE CHIP 120 OHM 2000MA 0603"
J1: library part J_A31727TR-ND, "CONN MINI USB RCPT RA TYPE B SMD"
J2 J5: library part J_HDR1X8_THRHOLE_VERT_FEMALE, "CONN HEADER FEMALE 8POS .1\" TIN"
J3: library part J_HDR1X10_THRHOLE_VERT_FEMALE, "CONN HEADER FEMALE 10POS.1\" TIN"
J4: "CONN HEADER FEMALE 6POS .1\" TIN"
J6 J7 J10 J12: "CONN HEADER .100\" 12POS TIN PCB"
J8: "CONN HEADER PH SIDE 2POS 2MM SMD"
J9 J14: "CONN HEADER 10POS DL UNSHRD SMD"
J11: "CONN RECEPT 8POS DUAL SMD"
J13: "CONN RECEPT 4ROW X 20POS .50\" SMT"
L1 L2: library part L_3.30UH_2A, "INDUCTOR POWER 3.3UH 2.0A SMD"
L3: "FERRITE CHIP 120 OHM 1.2A 0402"
LED1 LED2: "LED 1X0.5MM 570NM GN WTR CLR SMD"
R1: "RES 100K OHM 1/16W 1% 0402 SMD"
R2 R12 R13 R14 R15 R18 R19 R23 R24 R28 R29 R30 R31 R32 R33 R34 R35 R40 R41 R42 R43: "RES 10.0K OHM 1/16W 1% 0402 SMD"
R3 R11: "RES 332 OHM 1/16W 1% 0402 SMD"
R4: "RES 3.01K OHM 1/16W 1% 0402 SMD"
R5 R20 R22: "RES 1.00K OHM 1/16W 1% 0402 SMD"
R6: "RES 1.00 OHM 1/16W 1% 0402 SMD"
R7: "RES 324K OHM 1/10W 1% 0402 SMD"
R8: "RES 121K OHM 1/10W 1% 0402 SMD"
R9: "RES 15.0K OHM 1/10W 1% 0402 SMD"
R10: "RES 105K OHM 1/10W 1% 0402 SMD"
R16: "RES 49.9 OHM 1/16W 1% 0402 SMD"
R17 R25: library part R_0402_0.00, "RES 1.00 OHM 1/16W 1% 0402 SMD"
R21: "RES 1.00M OHM 1/4W 1% 1206 SMD"
R26 R27: "RES 22.0 OHM 1/16W 1% 0402 SMD"
R39: "RES 28.7K OHM 1/16W 1% 0402 SMD"
S1 S2 S3: "SWITCH LT 1.5MM HT 160GF SMD"
U1: library part U_LTC3566, "IC USB POWER MANAGER 24-QFN"
U2: "MCU ARM 1024KB FLASH 176UFBGA"
U3: library part U_W7200, "WIZNET 7200 MCU INT TCP/IP STACK"
Y1: library part Y_SMD_25.00MHZ_18PF, "CRYSTAL 25.000000 MHZ 8PF SMD"
Y2 Y3: library part Y_SMD_8.00MHZ_10PF, "CRYSTAL 8.000 MHZ 10PF SMD"

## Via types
v1: diameter 14, hole 6, Top Side to Bottom Side, 362 vias
v2: diameter 20, hole 8, Top Side to Bottom Side, 23 vias
v3: diameter 20, hole 10, Top Side to Bottom Side, 10 vias
v4: diameter 25.98, hole 12.99, Top Side to Bottom Side, tented top, 4 vias

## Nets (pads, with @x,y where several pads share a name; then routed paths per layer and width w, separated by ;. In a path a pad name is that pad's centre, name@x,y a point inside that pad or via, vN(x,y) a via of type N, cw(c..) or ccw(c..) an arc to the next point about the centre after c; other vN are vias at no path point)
A0: J4.1 U2.E2 | length 1232.8
  Top Side w5: U2.E2@2264.76,1138.78 2277.56,1125.98 2443.9,1125.98 v1(2501.48,1068.41)
  MidLayer1 w5: J4.1@2501.48,101.48 v1(2501.48,1068.41)
A1: J4.2 U2.H3 | length 1383.5
  Top Side w5: U2.H3@2239.17,1215.55 v1(2251.97,1228.35)
  MidLayer1 w5: J4.2@2400,100 2482.28,182.28 v1(2482.28,1163.55)
  Bottom Side w5: v1(2251.97,1228.35) 2264.76,1241.14 2404.69,1241.14 v1(2482.28,1163.55)
A2: J4.3 U2.H2 | length 1402.2
  Top Side w5: U2.H2@2264.76,1215.55 2277.56,1228.35 2443.9,1228.35 2450.3,1234.74 v1(2463.09,1234.74)
  MidLayer1 w5: J4.3@2300,100 2463.09,263.09 v1@2463.09,1228.35
A3: J4.4 U2.J2 | length 1504.2
  Top Side w5: U2.J2@2264.76,1241.14 2277.56,1253.94 2401.94,1253.94 2428,1280 v1(2443.9,1280)
  MidLayer1 w5: J4.4@2200,100 2251.58,151.58 2299.25,151.58 2443.9,296.22 v1(2443.9,1280)
A4: J4.5 U2.J3 | length 1536.5
  Top Side w5: U2.J3@2239.17,1241.14 v1(2251.97,1253.94)
  MidLayer1 w5: J4.5@2100,100 2176.58,176.58 2274.25,176.58 2424.7,327.03 v1(2424.7,1253.94)
  Bottom Side w5: v1(2251.97,1253.94) 2296.75,1253.94 v1(2424.7,1253.94)
A5: J4.6 U2.K3 | length 1605.6
  Top Side w5: U2.K3@2239.17,1266.73 2251.97,1279.53 v1(2405.51,1279.53)
  MidLayer1 w5: J4.6@2000,100 2101.58,201.58 2249.25,201.58 2405.51,357.84 v1(2405.51,1279.53)
AV3P3: C14.2 R13.1 R14.1 U1.1 | length 928.2
  Top Side w10: C14.2@1431,455 v2(1464,455) 1481,455 1490.04,464.04 U1.1@1490.04,481.22
  Bottom Side w5: v2(1464,455) 1463.25,455.75 1463.25,537.99 1433.25,567.99 1209.25,567.99 1184.25,592.99 1184.25,652.99 1219.25,687.99 R14.1@1532.94,687.99 R13.1@1532.94,647.99
BOOT0: C1.2 R1.2 S1.1 U2.D6 U2.D10 U3.35 | length 2172.5
  Top Side w5: S1.1@229.92,816.24 C1.2@294.29,816.24 R1.2@339.07,816.24 v1@387.83,816.24 ; v1(812.99,1013.29) U3.35@812.99,1055.61 ; v1(2047.24,1125.98) U2.D10@2060.04,1113.19 2072.83,1100.39 2149.61,1100.39 U2.D6@2162.4,1113.19
  MidLayer2 w5: v1(387.83,816.31) 707.31,816.31 812.99,921.99 v1(812.99,1013.29) 831.7,1032 1953.26,1032 v1(2047.24,1125.98)
BOOT1: J10.1 R19.1 U2.M6 U3.14 | length 2489.8
  Top Side w5: R19.1@714,1775.35 714,1743 705,1734 659,1734 J10.1@594,1669 748.03,1514.97 U3.14@748.03,1429.63 ; v1(2149.61,1356.3) 2149.61,1330.71 U2.M6@2162.4,1317.91
  MidLayer2 w5: J10.1@594,1669 658.76,1733.76 v1(2149.61,1733.76)
  MidLayer1 w5: v1(2149.61,1356.3) v1(2149.61,1733.76)
C\O\M\M\_\R\S\T\: C59.2 S3.2 U3.6 | length 604.7
  Top Side w5: v1(921.26,1387.3) U3.6@921.26,1429.63 ; v1(1034.25,1795.74) S3.2@1141.41,1795.74
  Bottom Side w5: v1(921.26,1387.3) 921.26,1498.59 1034.25,1611.58 v1(1034.25,1795.74)
COMM_BOOT0: R43.2 U3.38 | length 190.4
  Top Side w5: R43.2@790,901.65 790,939 877.95,1026.95 U3.38@877.95,1055.61
COMM_TCK: J14.4 U3.31 | length 303
  Top Side w5: J14.4@510,931.77 510,992 529,1011 573,1011 617.61,1055.61 U3.31@726.38,1055.61
COMM_TDI: J14.8 U3.32 | length 244.3
  Top Side w5: J14.8@610,931.77 610,989 629,1008 737,1008 748.03,1019.03 U3.32@748.03,1055.61
COMM_TDO: J14.6 U3.33 | length 473.9
  Top Side w5: v1(560,860) J14.6@560,931.77 ; U3.33@769.69,1055.61 v1(769.69,1097.93)
  Bottom Side w5: v1(560,860) 560,948 709.93,1097.93 v1(769.69,1097.93)
COMM_TMS: J14.2 U3.29 | length 352.3
  Top Side w5: J14.2@460,931.77 460,1011 474,1025 550,1025 637.7,1112.7 U3.29@690.94,1112.7
COMM_TRST: J14.10 U3.34 | length 209.2
  Top Side w5: J14.10@660,931.77 712.77,931.77 791.34,1010.34 U3.34@791.34,1055.61
COMM_UART1_RX: U2.R12 U3.26 | length 1514.7
  Top Side w5: v1(648.62,1177.66) U3.26@690.94,1177.66 ; v1(1996.06,1381.89) U2.R12@2008.86,1394.69
  Bottom Side w5: v1(648.62,1177.66) 661.91,1164.37 927.66,1164.37 946.85,1183.56 946.85,1202.76 968.09,1224 1108.84,1224 1266.73,1381.89 v1(1996.06,1381.89)
COMM_UART1_TX: U2.R13 U3.25 | length 1514.6
  Top Side w5: v1(648.62,1199.31) U3.25@690.94,1199.31 ; U2.R13@1983.27,1394.69 v1(1996.06,1407.48)
  Bottom Side w5: v1(648.62,1199.31) 675.2,1199.31 690.94,1183.56 914.86,1183.56 927.66,1196.36 927.66,1209.15 959.65,1241.14 1100.39,1241.14 1266.73,1407.48 v1(1996.06,1407.48)
COMM_VA3P3: C57.2 C58.2 FB1.2 U3.57 | length 192.2
  Top Side w10: U3.57@1064.96,1329.23 FB1.2@1257.19,1329.23
COMM_XI: C60.2 U3.4 Y2.1 | length 400.1
  Top Side w10: U3.4@964.57,1429.63 964.57,1537.43 925,1577 925,1649 981.41,1705.41 Y2.1@987.9,1705.41 C60.2@1066,1705.41
COMM_XO: C61.2 U3.5 Y2.3 | length 318.3
  Top Side w10: C61.2@748,1610.93 Y2.3@830.42,1610.93 844.07,1610.93 942.91,1512.09 U3.5@942.91,1429.63
D0: J5.1 U2.R2 | length 740.8
  Top Side w5: U2.R2@2264.76,1394.69 2264.76,1552.09 v1(2299.25,1586.58)
  MidLayer1 w5: v1(2299.25,1586.58) 2309.25,1596.58 2309.25,1874.21 2373.52,1938.48 2438.48,1938.48 J5.1@2500,2000
D1: J5.2 U2.P2 | length 1045.5
  Top Side w5: U2.P2@2264.76,1369.09 2277.56,1381.89 2277.56,1529.04 v1(2335.14,1586.61)
  MidLayer1 w5: v1(2335.14,1586.61) 2335.14,1868.11 2386.32,1919.29 2495.08,1919.29 2559.06,1983.27 2559.06,2034.45 2533.46,2060.04 2460.04,2060.04 J5.2@2400,2000
D2: J5.3 U2.N3 | length 681.7
  Top Side w5: U2.N3@2239.17,1343.5 v1(2251.97,1356.3)
  MidLayer1 w5: v1(2251.97,1356.3) 2251.97,1951.97 J5.3@2300,2000
D3: J5.4 J13.14 U2.N2 | length 1618.4
  Top Side w5: U2.N2@2264.76,1343.5 v1(2277.56,1356.3) ; v1@2284.55,1751.58 J13.14@2974.55,1751.58
  MidLayer1 w5: J5.4@2200,2000 2266.44,2066.44 2322.34,2066.44 2347.93,2040.85 2347.93,1964.07 2283.96,1900.1 2283.96,1751.58 2264.76,1732.39 2264.76,1369.09 v1(2277.56,1356.3)
  other v1: 2284.25,1751.58
D4: J5.5 R34.2 U2.A6 | length 1642.7
  Top Side w5: v1(2111.22,985.24) U2.A6@2162.4,1036.42
  MidLayer2 w5: v1(1900.1,959.65) 2085.63,959.65 v1(2111.22,985.24)
  MidLayer1 w5: v1(1900.1,959.65) 1900.1,1800.1 J5.5@2100,2000
  Bottom Side w5: R34.2@2100,1774.61 J5.5@2100,2000
D5: J5.6 U2.B6 | length 1533.1
  Top Side w5: v1(2162.4,972.44) 2175.2,985.24 2175.2,1049.21 U2.B6@2162.4,1062.01
  MidLayer2 w5: v1(1880.91,926.58) 2037.13,926.58 2048.84,914.86 2104.82,914.86 v1(2162.4,972.44)
  MidLayer1 w5: v1(1880.91,926.58) 1880.91,1880.91 J5.6@2000,2000
D6: J5.7 U2.F15 | length 940.9
  Top Side w5: v1(1829.72,1234.74) 1829.72,1209.15 1874.51,1164.37 U2.F15@1932.09,1164.37
  MidLayer1 w5: v1(1829.72,1234.74) 1829.72,1929.72 J5.7@1900,2000
D7: J5.8 U2.E15 | length 1022.4
  Top Side w5: v1(1752.95,1234.74) 1752.95,1202.76 1816.93,1138.78 U2.E15@1932.09,1138.78
  MidLayer1 w5: v1(1752.95,1234.74) 1752.95,1952.95 J5.8@1800,2000
D8: J3.1 R15.2 U2.D15 | length 1172.5
  Top Side w5: R15.2@1669.78,1234.74 v1(1714.57,1234.74) 1714.57,1125.98 1727.36,1113.19 U2.D15@1932.09,1113.19
  MidLayer1 w5: J3.1@1640,2000 1714.57,1925.43 v1(1714.57,1234.74)
D9: J3.2 U2.B5 | length 2044.2
  Top Side w5: U2.B5@2187.99,1062.01 2200.79,1049.21 2200.79,1015.04 2224.25,991.58 2224.25,876.58 v1(2199.25,851.58)
  MidLayer2 w5: v1@1540,851.48 v1@2199.25,851.48
  MidLayer1 w5: v1(1540,850.89) J3.2@1540,2000
D10: J3.3 U2.N4 | length 1415.1
  Top Side w5: v1(1439.47,1810.53) J3.3@1439.47,1999.47 ; v1(2200.79,1356.3) U2.N4@2213.58,1343.5
  MidLayer2 w5: v1(1439.47,1810.53) v1(2187.99,1810.53)
  MidLayer1 w5: v1(2187.99,1810.53) 2187.99,1369.09 v1(2200.79,1356.3)
D11: J3.4 J13.13 U2.R3 | length 2240.2
  Top Side w5: J3.4@1340,2000 1343.5,1996.5 v1(1343.5,1874.51) ; v1(2232.78,1586.61) 2232.78,1567.42 2239.17,1561.02 U2.R3@2239.17,1394.69 ; v1(2232.78,1726.58) J13.13@2974.25,1726.58
  MidLayer2 w5: v1(1343.5,1874.51) v1(2232.78,1874.51)
  MidLayer1 w5: v1(2232.78,1586.61) v1(2232.78,1874.51)
D12: J3.5 U2.P3 | length 1674
  Top Side w5: U2.P3@2239.17,1369.09 2251.97,1381.89 2251.97,1593.01 v1(2283.96,1625)
  MidLayer2 w5: v1(1273.13,1625) v1(2283.96,1625)
  MidLayer1 w5: J3.5@1240,2000 1273.13,1966.87 v1(1273.13,1625)
D13: J3.6 J13.61 LED1.2 U2.P4 | length 5961
  Top Side w5: LED1.2@74.31,364.67 v3(74.31,426.18) ; v1(1138.78,1842.52) J3.6@1138.78,1998.78 ; v1(2207.18,1586.61) 2207.18,1554.63 2226.38,1535.43 2226.38,1381.89 U2.P4@2213.58,1369.09 ; v1(2324.25,526.58) J13.61@2974.25,526.58
  MidLayer2 w5: v1(128,1809) 161.52,1842.52 v1(1138.78,1842.52) v1(2207.18,1842.52)
  MidLayer1 w5: v3(74.31,426.18) 74.31,1309.06 127.95,1362.7 v1(128,1809) ; v1(2207.18,1842.52) v1(2207.18,1586.61) 2207.18,1381.89 2226.38,1362.7 2226.38,1330.71 2296.75,1260.33 2296.75,1078.49 2324.25,1050.99 v1(2324.25,526.58)
D14: J3.8 U2.F14 | length 1810.5
  Top Side w5: v1(940,1823.78) J3.8@940,2000 ; v1(1791.34,1234.74) 1791.34,1209.15 1848.92,1151.57 1944.88,1151.57 U2.F14@1957.68,1164.37
  MidLayer2 w5: v1@940.45,1823.33 985.24,1778.54 v1(1791.34,1778.54)
  MidLayer1 w5: v1(1791.34,1234.74) v1(1791.34,1778.54)
D15: J3.9 J13.26 U2.J4 | length 2877.4
  Top Side w5: U2.J4@2213.58,1241.14 2226.38,1253.94 v1(2226.38,1279.53) ; v1(2574.25,1451.58) J13.26@2974.25,1451.58
  MidLayer2 w5: J3.9@840,2000 914.31,1925.69 v1(1676.18,1925.69) ; v1(1676.18,1362.7) 1989.67,1362.7 2015.26,1337.11 2066.44,1337.11 2117.62,1285.93 2194.39,1285.93 2200.79,1279.53 v1(2226.38,1279.53)
  MidLayer1 w5: v1(1676.18,1362.7) v1(1676.18,1925.69)
  Bottom Side w5: v1(2226.38,1279.53) 2239.17,1292.32 2296.75,1292.32 2431.1,1426.67 2549.35,1426.67 v1(2574.25,1451.58)
D16: J3.10 J13.25 U2.H4 | length 2980.1
  Top Side w5: v1(2200.79,1228.35) U2.H4@2213.58,1215.55 ; v1(2599.25,1426.58) J13.25@2974.25,1426.58
  MidLayer2 w5: J3.10@740,2000 839.9,1900.1 v1(1656.99,1900.1) ; v1(1656.99,1343.5) 1957.68,1343.5 1976.87,1324.31 2002.46,1324.31 2053.64,1273.13 2156,1273.13 v1(2200.79,1228.35)
  MidLayer1 w5: v1(1656.99,1343.5) v1(1656.99,1900.1)
  Bottom Side w5: v1(2200.79,1228.35) 2251.97,1279.53 2309.55,1279.53 2437.5,1407.48 2580.15,1407.48 v1(2599.25,1426.58)
DCMI_D0: J13.64 U2.H15 | length 1816.4
  Top Side w5: v1(1919.29,501.58) J13.64@2974.25,501.58 ; v1(1919.29,1228.35) U2.H15@1932.09,1215.55
  MidLayer1 w5: v1(1919.29,501.58) 1919.29,566.54 1899.25,586.58 1899.25,906.58 1919.29,926.62 v1(1919.29,1228.35)
DCMI_D1: J13.63 U2.G15 | length 1901.4
  Top Side w5: v1(1861.71,1209.15) 1880.91,1189.96 U2.G15@1932.09,1189.96 ; v1(1899.25,476.58) J13.63@2974.25,476.58
  MidLayer1 w5: v1(1861.71,1209.15) 1861.71,514.12 v1(1899.25,476.58)
DCMI_D2: J13.66 U2.G14 | length 1829
  Top Side w5: v1(1939.25,451.58) J13.66@2974.25,451.58 ; v1(1944.88,1202.76) U2.G14@1957.68,1189.96
  MidLayer1 w5: v1(1939.25,451.58) 1939.25,481.58 1951.28,493.61 1951.28,575.79 1924.25,602.81 1924.25,896.58 1944.88,917.21 v1(1944.88,1202.76)
DCMI_D3: J13.65 U2.A3 | length 1295.2
  Top Side w5: U2.A3@2239.17,1036.42 2274.01,1001.58 2299.25,1001.58 v1(2349.25,951.58) ; v1(2349.25,426.58) J13.65@2974.25,426.58
  MidLayer1 w5: v1(2349.25,426.58) v1(2349.25,951.58)
DCMI_D4: J13.68 R35.2 U2.B13 | length 1921.4
  Top Side w5: v1(1842.52,953.25) 1874.51,985.24 1938.48,985.24 1970.47,1017.22 1970.47,1049.21 U2.B13@1983.27,1062.01 ; R35.2@1880.91,360.73 1880.91,396.65 1885.83,401.58 v1(1924.25,401.58) J13.68@2974.25,401.58
  MidLayer1 w5: v1(1842.52,953.25) 1842.52,483.31 v1(1924.25,401.58)
DCMI_D5: J13.67 U2.D4 | length 1447.1
  Top Side w5: U2.D4@2213.58,1113.19 v1(2226.38,1100.39) ; v1(2299.25,376.58) J13.67@2974.25,376.58
  MidLayer1 w5: v1(2226.38,1100.39) 2299.25,1027.52 v1(2299.25,376.58)
DCMI_D6: J13.70 U2.A5 | length 1449.9
  Top Side w5: U2.A5@2187.99,1036.42 2187.99,1002.84 2200.79,990.04 v1(2200.79,953.25) ; v1(2224.25,351.58) J13.70@2974.25,351.58
  MidLayer1 w5: v1(2200.79,953.25) 2224.25,929.78 v1(2224.25,351.58)
DCMI_D7: J13.69 U2.B4 | length 1475.3
  Top Side w5: U2.B4@2213.58,1062.01 2226.38,1049.21 2226.38,1019.45 2249.17,996.66 v1(2249.17,978.84) ; v1(2249.17,326.58) J13.69@2974.25,326.58
  MidLayer1 w5: v1(2249.17,326.58) v1(2249.17,978.84)
DCMI_D8: J13.72 U2.B14 | length 1993
  Top Side w5: v1(1791.34,998.03) 1842.52,1049.21 1944.88,1049.21 U2.B14@1957.68,1062.01 ; v1(1926.58,301.58) J13.72@2974.25,301.58
  MidLayer1 w5: v1(1791.34,998.03) 1791.34,436.82 v1(1926.58,301.58)
DCMI_D9: J13.71 U2.A12 | length 1737.9
  Top Side w5: U2.A12@2008.86,1036.42 v1(2021.65,1049.21) ; v1(2060.04,276.58) J13.71@2974.25,276.58
  MidLayer1 w5: v1(2021.65,1049.21) 2021.65,1023.62 2044.25,1001.02 2044.25,976.58 2054,966.83 2054,734 2074.25,713.75 2074.25,596.58 2053.64,575.97 2053.64,282.98 v1(2060.04,276.58)
DCMI_D10: J13.74 U2.C13 | length 1848.9
  Top Side w5: v1(1970.47,275.1) 2010.93,275.1 2034.45,251.58 J13.74@2974.25,251.58 ; v1(1970.47,1074.8) U2.C13@1983.27,1087.6
  MidLayer1 w5: v1(1970.47,275.1) 1970.47,605.36 1949.25,626.58 1949.25,893.64 1970.47,914.86 v1(1970.47,1074.8)
DCMI_D11: J13.73 U2.D12 | length 1852.9
  Top Side w5: v1(1996.06,1100.39) U2.D12@2008.86,1113.19 ; v1(2699.25,226.58) J13.73@2974.25,226.58
  MidLayer2 w5: v1(2002.46,249.51) 2676.32,249.51 v1(2699.25,226.58)
  MidLayer1 w5: v1(1996.06,1100.39) 1996.06,939.77 2002.46,933.37 v1(2002.46,249.51)
DCMI_D12: J13.76 U2.P6 | length 2062
  Top Side w5: v1(2124.37,1382.24) 2149.25,1382.24 U2.P6@2162.4,1369.09 ; v1(2199.25,226.58) 2224.25,201.58 J13.76@2974.25,201.58
  MidLayer1 w5: v1(2124.37,1382.24) 2104.82,1362.7 2104.82,1337.11 2111.22,1330.71 2149.61,1330.71 2175.2,1305.12 2175.2,1125.98 2194.39,1106.79 2194.39,1094 2185,1084.61 2185,820.83 2199.25,806.58 v1(2199.25,226.58)
DCMI_D13: J13.75 U2.B7 | length 1722.5
  Top Side w5: v1(2124.02,1074.8) U2.B7@2136.81,1062.01 ; v1(2149.25,226.58) 2199.25,176.58 J13.75@2974.25,176.58
  MidLayer1 w5: v1(2124.02,1074.8) 2144.25,1054.57 2144.25,906.58 2149.25,901.58 v1(2149.25,226.58)
DCMI_HSYNC: J13.59 U2.M12 | length 1652.7
  Top Side w5: U2.M12@2008.86,1317.91 2021.65,1305.12 v1(2021.65,1279.53) ; v1(2119.25,576.58) J13.59@2974.25,576.58
  MidLayer1 w5: v1(2021.65,1279.53) 2040.85,1260.33 2040.85,1145.18 2028.05,1132.38 2028.05,1119.59 2053.64,1094 2053.64,1036.42 2092.03,998.03 2092.03,966.04 2119.25,938.82 v1(2119.25,576.58)
DCMI_VSYNC: J13.62 U2.C4 | length 1261.1
  Top Side w5: U2.C4@2213.58,1087.6 v1(2226.38,1074.8) ; v1(2274.25,551.58) J13.62@2974.25,551.58
  MidLayer1 w5: v1(2226.38,1074.8) 2274.25,1026.93 v1(2274.25,551.58)
ETH_RX_D0: J13.15 U2.N5 | length 1129.1
  Top Side w5: U2.N5@2187.99,1343.5 2175.2,1356.3 2175.2,1529.04 2162.4,1541.83 2162.4,1631.4 2207.58,1676.58 J13.15@2974.25,1676.58
ETH_RX_D1: J13.18 U2.P5 | length 1060
  Top Side w5: U2.P5@2187.99,1369.09 2200.79,1381.89 2200.79,1541.83 2187.99,1554.63 2187.99,1618.6 2220.97,1651.58 J13.18@2974.25,1651.58
ETH_TX_CLK: J13.24 U2.D1 | length 1232.1
  Top Side w5: U2.D1@2290.35,1113.19 2397.64,1113.19 2529.25,981.58 2754.25,981.58 v1(2774.25,1001.58) ; v1(2824.25,1501.58) J13.24@2974.25,1501.58
  MidLayer1 w5: v1(2774.25,1001.58) 2799.25,1001.58 2824.25,1026.58 v1(2824.25,1501.58)
ETH_TX_D0: J13.20 U2.A8 | length 1458.8
  Top Side w5: v1(2098.42,1023.62) U2.A8@2111.22,1036.42 ; v1(2764.25,1601.58) J13.20@2974.25,1601.58
  MidLayer2 w5: v1(2098.42,1023.62) 2117.62,1042.81 2250.49,1042.81 2314.25,1106.58 2738.87,1106.58 v1(2764.25,1081.2)
  MidLayer1 w5: v1@2764.25,1081.58 v1(2764.25,1601.58)
ETH_TX_D1: J13.19 U2.A7 | length 1419.8
  Top Side w5: v1(2124.02,1023.62) U2.A7@2136.81,1036.42 ; v1(2784.25,1576.58) J13.19@2974.25,1576.58
  MidLayer2 w5: v1(2124.02,1023.62) 2271.3,1023.62 2309.25,1061.58 2399.25,1061.58 2424.25,1086.58 2699.25,1086.58 2724.25,1061.58 v1(2784.25,1061.58)
  MidLayer1 w5: v1(2784.25,1061.58) v1(2784.25,1576.58)
ETH_TX_EN: J13.21 U2.B9 | length 1500.9
  Top Side w5: v1(2072.83,978.84) 2072.83,1049.21 U2.B9@2085.63,1062.01 ; v1(2804.25,1526.58) J13.21@2974.25,1526.58
  MidLayer2 w5: v1(2072.83,978.84) 2095.57,1001.58 2724.25,1001.58 v1(2749.25,1026.58)
  MidLayer1 w5: v1(2749.25,1026.58) 2789.25,1026.58 2804.25,1041.58 v1(2804.25,1526.58)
